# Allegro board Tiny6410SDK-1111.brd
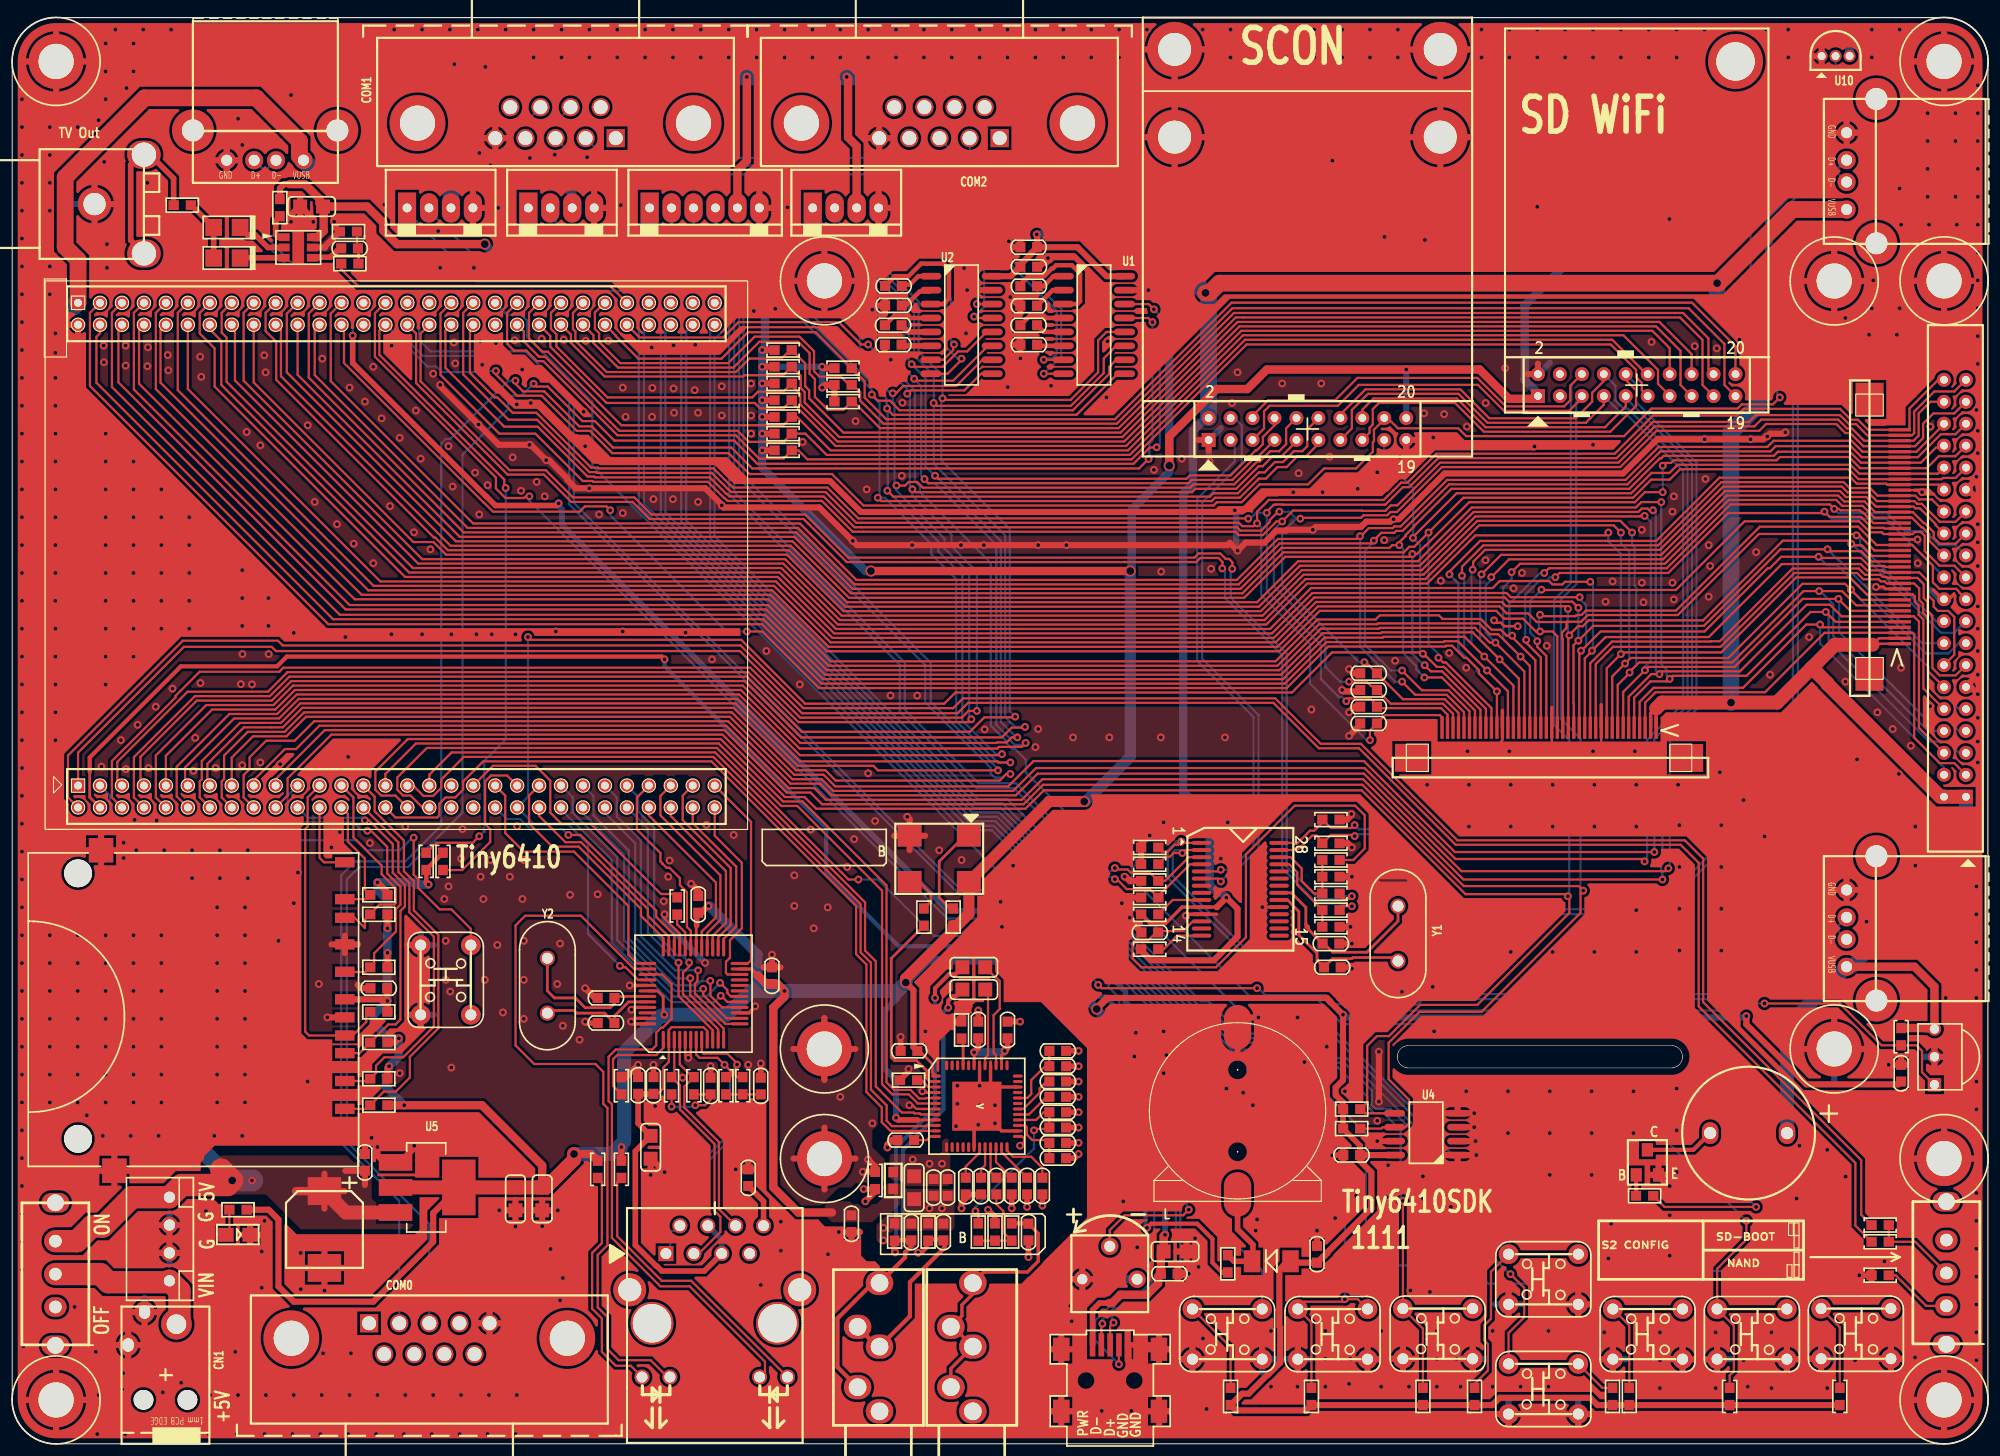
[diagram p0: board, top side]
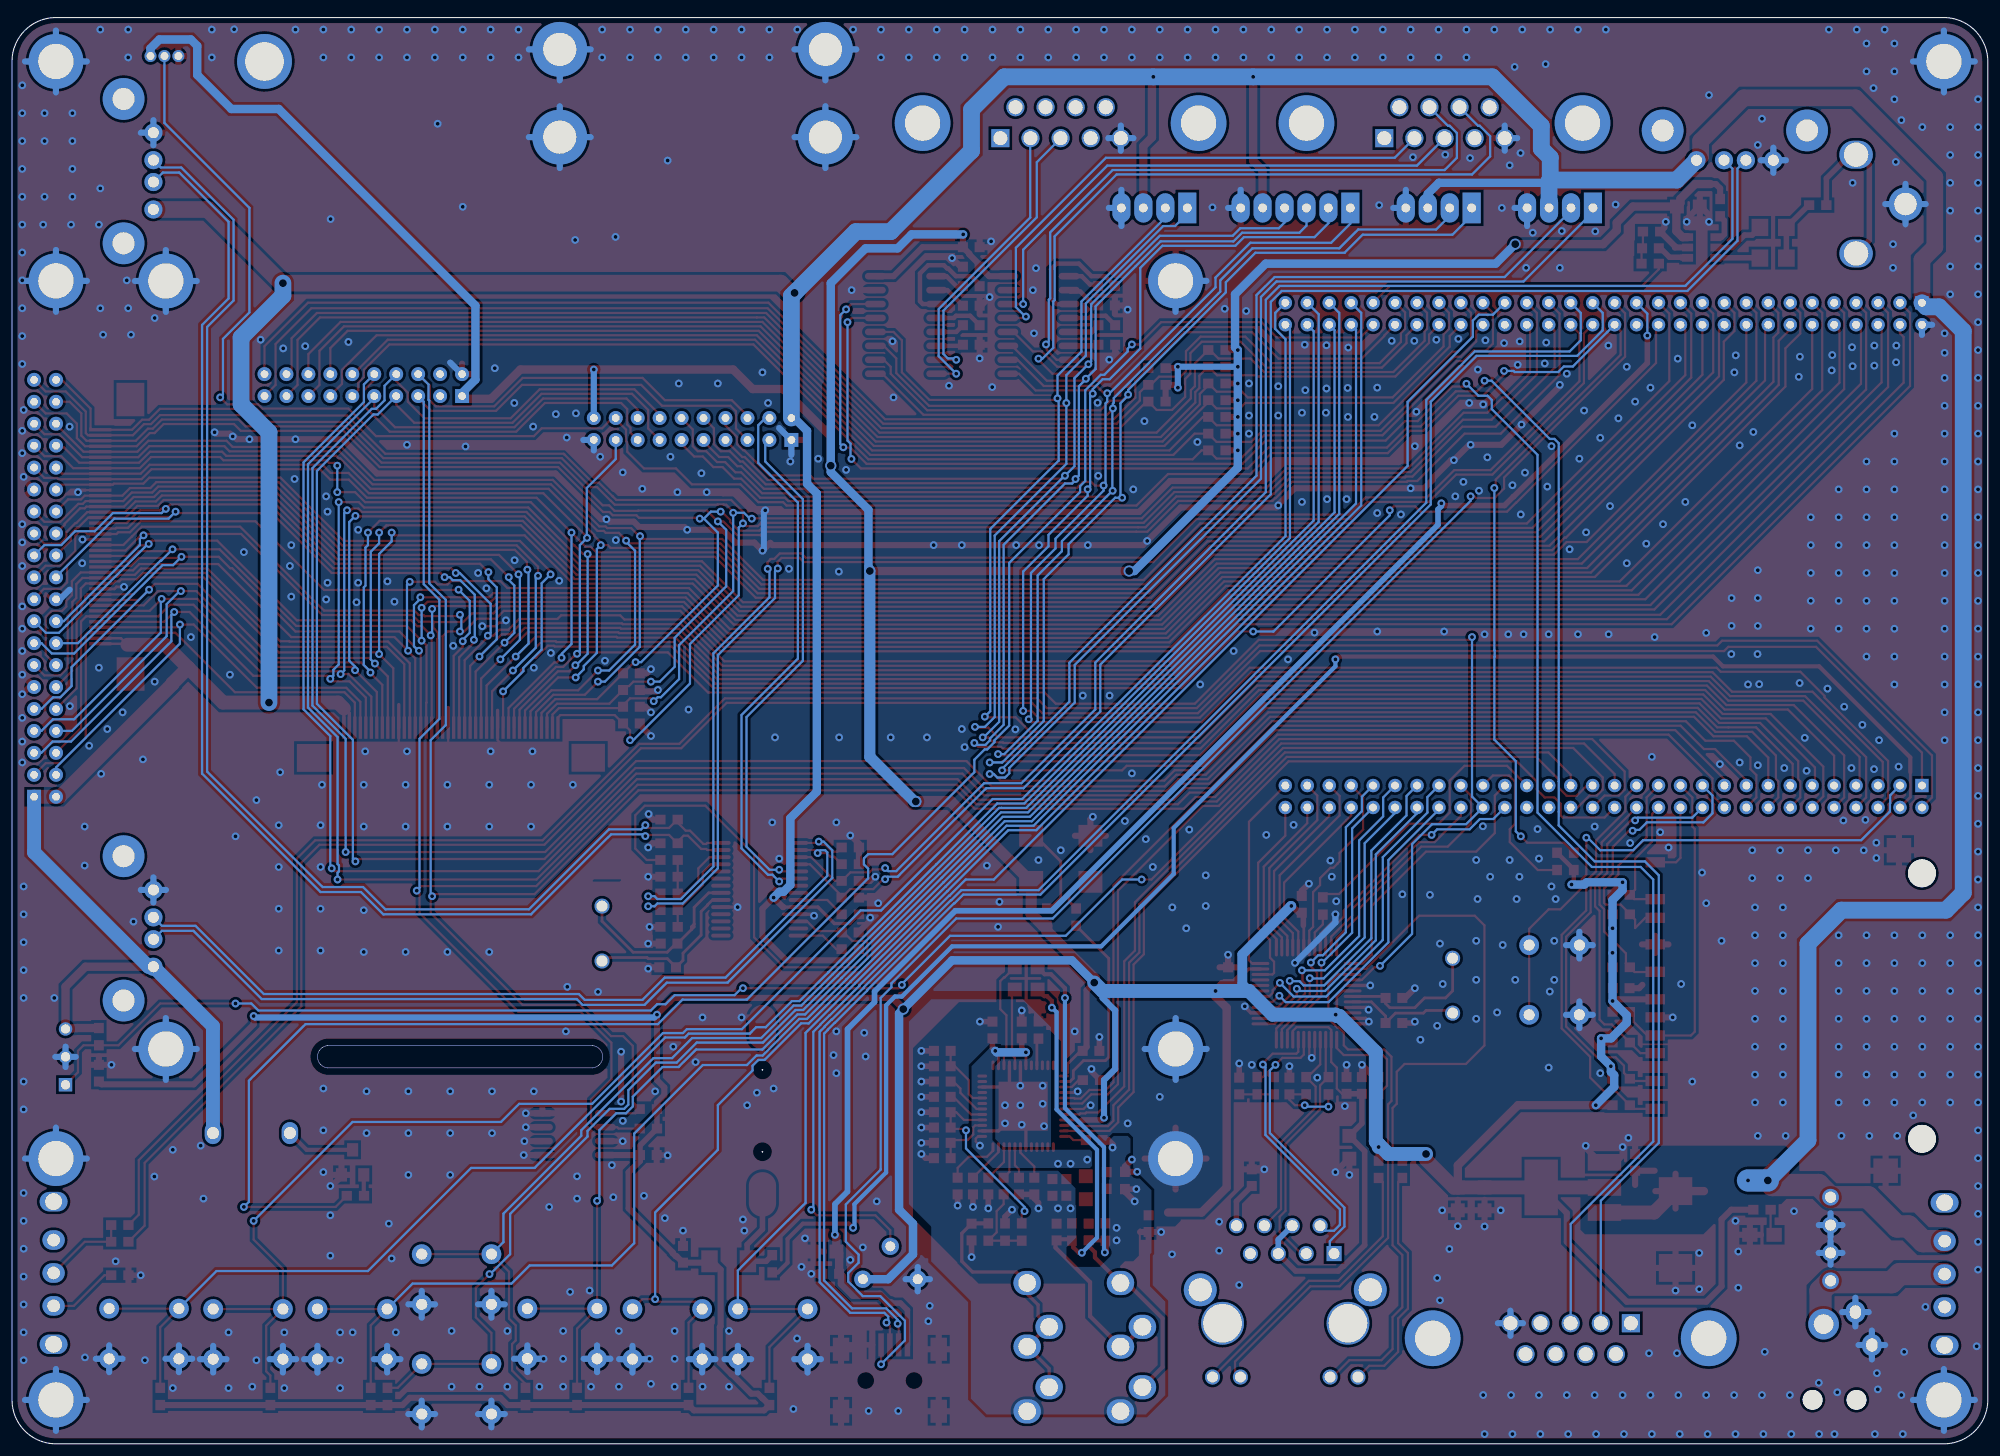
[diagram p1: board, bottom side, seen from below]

Outline 180 x 130 mm; copper layers: TOP, BOTTOM. Coordinates in mm from the lower left corner of the outline.
Outline path: 127.13,34.26 arc(126.19,35.28) 127.13,36.3 151.26,36.3 arc(152.17,35.28) 151.26,34.26 127.13,34.26

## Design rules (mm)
net group DIFFPAIR1: nets OTGDM OTGDP
net group DIFFPAIR2: nets USBDN USBDP
net group DIFFPAIR4: nets DM9000_TX+ DM9000_TX-
net group DIFFPAIR7: nets DM9000_RX+ DM9000_RX-
net group DIFFPAIR8: nets SUB_DM1 SUB_DP1
net group DIFFPAIR9: nets USB_D+ USB_D-
net group DIFFPAIR10: nets SUB_DM2 SUB_DP2
net group DIFFPAIR11: nets SUB_DM3 SUB_DP3
net group PWR: nets GND GND_AC97 VDD5V VDD33V

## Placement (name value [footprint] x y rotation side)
BAT1  BATTERY  [BAT600]  111.63 22.73 180 top
BUZZER  -  [SPEAKER]  161.44 28.32 180 top
C1  47uF/10V  [CAPSOP]  28.45 23.03 270 top
C2  47uF/10V  [C0805]  48.29 23.37 270 top
C3  104  [C0603]  32.13 24.89 90 top
C4  104  [0603A]  81.05 105.54 180 top
C5  104  [0603A]  81.05 103.76 180 top
C6  104  [0603A]  81.03 100.18 180 top
C7  104  [0603A]  79.5 101.96 0 top
C8  104  [0603A]  62.5 48.41 90 top
C14  104  [C0603]  93.37 107.29 180 top
C15  104  [C0603]  32.64 41.53 0 top
C16  104  [C0603]  76.45 19.3 90 top
C17  10uF/16V  [C0805]  104.9 17.53 0 top
C18  104  [C0603]  106.17 15.49 180 top
C20  104  [C0603]  118.87 18.03 270 top
C21  104  [C0603]  121.27 26.32 0 top
C22  104  [C0603]  83.95 22.61 90 top
C23  104  [C0603]  96.01 35.81 180 top
C24  104  [C0603]  85.22 22.61 90 top
C25  104  [C0603]  96.01 26.04 180 top
C26  104  [C0603]  96.01 28.83 180 top
C27  220pF  [C0603]  92.58 18.54 90 top
C28  220pF  [C0603]  84.84 18.54 90 top
C29  220pF  [C0603]  81.92 18.54 90 top
C30  104  [C0603]  104.39 46.61 180 top
C31  15pF  [C0603]  119.38 45.59 0 top
C32  10uF/10V  [C0805]  82.17 24.38 270 top
C33  1uF  [C0603]  93.85 24.26 270 top
C34  1uF  [C0603]  92.46 24.26 270 top
C35  104  [C0603]  57.02 33.43 270 top
C36  104  [C0603]  58.42 33.43 270 top
C37  1uF  [C0603]  89.66 24.26 270 top
C38  1uF  [C0603]  96.01 34.42 180 top
C39  1uF  [C0603]  96.01 27.43 180 top
C40  1uF  [C0603]  96.01 30.23 180 top
C41  47uF/10V  [C0805]  88.65 43.43 180 top
C42  47uF/10V  [C0805]  88.65 41.4 180 top
C43  100n  [C0603]  91.85 109.07 0 top
C44  104  [C0603]  31.5 108.97 180 top
C45  10uF/16V  [C0805]  28.32 112.78 180 top
C46  33uF  [C3216]  19.56 110.87 180 top
C47  33uF  [C3216]  19.56 108.08 180 top
C48  104  [C0603]  88.01 38.48 270 top
C49  104  [C0603]  90.68 38.48 270 top
C50  104  [C0603]  82.46 35.81 180 top
C51  104  [C0603]  88.27 22.73 90 top
C52  104  [C0603]  91.06 22.73 90 top
C53  104  [C0603]  86.87 22.73 90 top
C54  104  [0603A]  69.22 41.91 90 top
C55  104  [0603A]  93.37 105.51 180 top
C56  104  [0603A]  93.37 103.73 180 top
C57  104  [C0603]  96.01 31.62 180 top
C58  104  [0603A]  91.85 101.96 0 top
C59  104  [0603A]  93.37 100.18 180 top
C60  104  [C0603]  96.01 33.02 180 top
C61  104  [C0603]  80.64 27.69 0 top
C62  104  [C0603]  172.09 33.02 90 top
C64  15pF  [C0603]  119.51 43.43 0 top
C69  10nF  [0603A]  124.33 70.23 180 top
C70  10nF  [0603A]  124.33 67.18 180 top
C71  10nF  [0603A]  124.33 65.66 180 top
C72  10nF  [0603A]  124.33 68.71 180 top
C73  10uF/16V  [C0805]  45.85 23.37 270 top
C74  10uF/16V  [C0805]  58.17 28.07 270 top
C75  15pF  [C0603]  53.34 40.64 0 top
C76  15pF  [C0603]  53.34 38.35 0 top
C145  0.1uF  [C0603]  67.06 23.5 90 top
C148  104  [C0603]  68.2 33.38 270 top
C149  104  [C0603]  63.63 33.38 270 top
CN1  DC_JACK  [DC023B]  13.96 6.26 90 top
COM0  BOXCONN_DB9  [DB9RA_M]  38 10.99 90 top
COM1  BOXCONN_DB9  [DB9RA_M]  49.5 119.01 270 top
COM2  BOXCONN_DB9  [DB9RA_M]  84.47 119.01 270 top
CON1  CON4  [SIP4-FA2]  71.85 112.65 0 top
CON2  CON6  [SIP6-FA2]  63.07 112.65 0 top
CON3  CON4  [SIP4-FA2]  45.94 112.65 0 top
CON4  CON4  [SIP4-FA2]  34.89 112.65 0 top
CON5  HEADER 10X2  [SCON]  118 92.5 0 top
CON6  SD/MMC CARD  [NEWSD]  11.75 32.9 180 top
CON7  CON3  [TVOUT]  12 108.5 0 top
CON8  CON4  [CON4-B]  14.33 18.67 270 top
CON9  PHONEJACK STEREO SW  [EARJACK5]  78.92 15.83 270 top
CON10  PHONEJACK STEREO SW  [EARJACK5]  87.42 15.83 270 top
CON11  HEADER 10X2  [SDWIFI]  148 96.5 0 top
D1  1N4148  [D1206]  116.47 16.63 180 top
H1  CON1  [H1]  74 26 0 top
H2  CON1  [H1]  176 4 0 top
H3  CON1  [H1]  176 26 0 top
H4  CON1  [H1]  4 4 0 top
H5  CON1  [H1]  176 106 0 top
H6  CON1  [H1]  176 126 0 top
H7  CON1  [H1]  74 106 0 top
H8  CON1  [H1]  4 126 0 top
H9  CON1  [H1]  165.99 35.99 0 top
H10  CON1  [H1]  165.99 105.99 0 top
H11  CON1  [H1]  73.99 35.99 0 top
K1  -  [PUSHSW]  107.12 12.29 0 top
K2  -  [PUSHSW]  116.72 12.29 0 top
K3  -  [PUSHSW]  145.42 12.29 0 top
K4  -  [PUSHSW]  126.29 12.32 0 top
K5  -  [PUSHSW]  135.92 7.29 0 top
K6  -  [PUSHSW]  135.92 17.29 0 top
K7  -  [PUSHSW]  154.92 12.29 0 top
K8  -  [PUSHSW]  164.39 12.32 0 top
L1  F.B/120  [L0603]  80.26 24 90 top
LAN  -  [HR911105A]  64.01 21.49 180 top
LCD1  HEADER 20X2  [SMD40-0_5FA]  152.93 66.25 180 top
LCD2  HEADER 20X2  [SMD40-0_5FA]  172.93 69.76 90 top
LCD3  HEADER 20X2  [IDC40S]  177.99 58.97 90 top
LED_3V3  RED  [LED]  19.47 19.04 0 top
MINIUSB  USBOTG  [MINIUSB]  100.02 5.77 0 top
NOREF  -  []  -40.64 175.26 0 top
NOREF#2  -  []  0 0 0 top
Q1  9014  [SOT23FA]  148.97 25.65 0 top
R1  10K  [R0603]  37.72 53.09 90 top
R2  0R  [R0603]  170.18 18.41 0 top
R3  10K  [0603R]  33.4 39.37 0 top
R4  10K  [0603R]  33.4 50.04 0 top
R5  10K  [0603R]  122.03 28.73 180 top
R6  10K  [0603R]  33.4 48.26 0 top
R7  10K  [0603R]  33.4 43.43 0 top
R8  10K  [0603R]  122.03 30.51 180 top
R9  10K  [0603R]  33.4 36.58 0 top
R10  10K  [0603R]  33.4 33.27 0 top
R11  330  [0603R]  20.57 21.34 180 top
R12  10K  [0603R]  33.4 30.86 0 top
R13  100K  [0603R]  110.74 16.41 90 top
R14  0R  [R0603]  60.58 49.02 270 top
R15  6.8K,1%  [R0603]  55.5 32.64 270 top
R16  22R  [R0603]  120.14 48.64 180 top
R17  22R  [R0603]  120.14 50.16 180 top
R18  10K  [R0603]  70.23 90.55 180 top
R19  10K  [R0603]  70.23 93.6 180 top
R20  10K  [R0603]  70.23 96.65 180 top
R21  0R  [R0603]  170.18 19.94 0 top
R22  1K  [R0603]  170.18 15.37 180 top
R23  1.5K  [0603R]  148.72 22.61 180 top
R24  330R  [R0603]  53.34 25.02 90 top
R25  0R  [0603R]  91.06 19.3 270 top
R26  0R  [R0603]  78.61 24 270 top
R27  0R  [0603R]  83.06 48.01 90 top
R28  0R  [0603R]  81.66 33.15 180 top
R29  680  [0603R]  88.01 19.3 90 top
R30  47K  [0603R]  89.53 19.3 90 top
R31  47K  [0603R]  80.39 19.3 90 top
R32  47K  [0603R]  83.44 19.3 90 top
R33  10K  [0603R]  111 4.32 270 top
R34  100K  [0603R]  86.49 37.72 270 top
R35  10K  [0603R]  118.36 4.32 270 top
R36  10K  [0603R]  147.32 4.32 270 top
R37  10K  [0603R]  128.52 4.32 270 top
R38  10K  [0603R]  145.8 4.32 270 top
R39  330R  [R0603]  55.5 25.02 90 top
R40  10K  [0603R]  133.22 4.32 270 top
R41  4K7  [R0603]  39.24 53.09 90 top
R42  15K  [R0603]  103.63 48.26 0 top
R43  15K  [R0603]  103.63 45.09 0 top
R44  15K  [R0603]  120.14 54.74 0 top
R45  100K  [0603R]  85.72 48.01 270 top
R46  0R  [0603R]  15.49 112.9 180 top
R47  10K  [R0603]  156.46 4.32 270 top
R48  10K  [R0603]  166.5 4.32 270 top
R49  15K  [R0603]  120.14 56.9 0 top
R50  15K  [R0603]  103.63 54.36 180 top
R51  15K  [R0603]  103.63 52.83 180 top
R52  15K  [R0603]  103.63 51.31 180 top
R53  15K  [R0603]  103.63 49.78 180 top
R54  1K5  [R0603]  120.14 53.21 0 top
R59  50R  [0603R]  30.76 107.57 0 top
R60  150R  [0603R]  30.63 110.49 0 top
R61  4.7K  [0603R]  24.38 112.67 90 top
R62  51R  [R0603]  65.02 32.64 90 top
R66  51R  [R0603]  66.55 32.64 90 top
R67  51R  [R0603]  60.07 32.64 90 top
R68  51R  [R0603]  62.1 32.64 90 top
R71  10K  [R0603]  70.23 99.69 180 top
R72  10K  [R0603]  75.69 96.52 180 top
R73  10K  [R0603]  70.23 92.08 180 top
R74  10K  [R0603]  70.23 95.12 180 top
R75  10K  [R0603]  70.23 98.17 180 top
R76  10K  [R0603]  75.69 95 180 top
R77  10K  [R0603]  75.69 98.04 180 top
R78  10K  [R0603]  172.09 37.11 270 top
R79  15K  [R0603]  120.14 51.69 180 top
R80  15K  [R0603]  120.14 47.12 180 top
RST  -  [PUSHSW]  41.78 45.86 270 top
S1  CON5  [SW35]  3.94 15.49 270 top
S2  CON5  [SW35]  176.21 15.6 270 top
TINY6410  -  [TINY6410]  3 56 0 top
U1  MAX3232CSE  [SOP16]  95.76 106.43 0 top
U2  MAX3232CSE  [SOP16]  83.69 106.43 0 top
U4  AT24LC04  [SOP8]  131.68 26.32 180 top
U5  AMS1086CM-3.3  [SOT223S]  35.43 25.65 270 top
U6  UDA1341TS  [TSSOP28]  111.89 50.55 270 top
U7  WM9714LGEFL  [QFN48-19P7-TH]  87.88 30.77 270 top
U8  DM9000AEP  [LQFP48FA]  62.07 41.03 0 top
U9  NJM2561F1  [SOT-23-6]  26.06 109.04 270 top
U10  DS18B20  [TO-92B]  166.12 126.49 0 top
U12  IRM3638  [LEDIR-IRM3638]  175.12 35.27 90 top
USBH1  USB Port A type  [USB-A2]  167.12 112.5 270 top
USBH2  USB Port A type  [USB-A2]  167.12 43.48 270 top
USBH3  USB Port A type  [USB-A2]  26.54 116.99 0 top
W1  10K  [VR3_7X7]  98.85 16 0 top
Y1  12MHz  [OSC2PR-1]  126.25 44.07 90 top
Y2  25MHz  [OSC2PR-1]  48.76 44.2 270 top
Y5  24.576MHz  [Y7050]  87.35 55.57 180 top

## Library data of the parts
BAT1 = BAT600
BUZZER = SPEAKER
C1 = CAPSOP
C2 C73 C74 = C0805
C3 C14-C16 C18 C20-C31 C33-C40 C43 C44 C48-C53 C57 C60-C62 C64 C75 C76 C145 C148 C149 = C0603
C4-C8 C54-C56 C58 C59 C69-C72 = 0603A
C17 C32 C41 C42 C45 = C3216
C46 C47 = C1210
CN1 = DC023B
COM0-COM2 = DB9RA_M
CON1 CON3 CON4 = SIP4-FA2
CON2 = SIP6-FA2
CON5 = SCON
CON6 = NEWSD
CON7 = TVOUT
CON8 = CON4-B
CON9 CON10 = EARJACK5
CON11 = SDWIFI
D1 = D1206
H1-H11 = H1
K1-K8 RST = PUSHSW
L1 = L0603
LAN = HR911105A
LCD1 LCD2 = SMD40-0_5FA
LCD3 = IDC40S
LED_3V3 = LED
MINIUSB = MINIUSB
Q1 = SOT23FA
R1 R2 R14-R22 R24 R26 R39 R41-R44 R47-R54 R62 R66-R68 R71-R80 = R0603
R3-R13 R23 R25 R27-R38 R40 R45 R46 R59-R61 = 0603R
S1 S2 = SW35
TINY6410 = TINY6410
U1 U2 = SOP16
U4 = SOP8
U5 = SOT223S
U6 = TSSOP28
U7 = QFN48-19P7-TH
U8 = LQFP48FA
U9 = SOT-23-6
U10 = TO-92B
U12 = LEDIR-IRM3638
USBH1-USBH3 = USB-A2
W1 = VR3_7X7
Y1 Y2 = OSC2PR-1
Y5 = Y7050

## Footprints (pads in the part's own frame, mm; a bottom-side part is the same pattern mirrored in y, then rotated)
0603A
  rect 0.914x0.914 smd: 1(0,0) 2(1.524,0)
0603R
  rect 0.94x0.889 smd: 1(-0.787,0) 2(0.787,0)
BAT600
  oval 2.489x4.064 smd: 1(0,0) 2(0,-15.24)
  round 0.127 hole 1.194: 3(0,-3.886) 4(0,-11.354)
C0603
  rect 0.914x0.914 smd: 1(0,0) 2(1.524,0)
C0805
  rect 1.27x1.27 smd: 1(0,0) 2(2.083,0)
C3216
  rect 1.524x1.575 smd: 1(-1.206,0) 2(1.206,0)
CAPSOP
  rect 2.54x3.048 smd: 1(0,0) 2(7,0)
CON4-B
  round 1.524 hole 1.016: 1(-3.81,0) 2(-1.27,0) 3(1.27,0) 4(3.81,0)
D1206
  rect 1.5x2 smd: 1(0.009,-0.006) 2(3.51,-0.006)
DB9RA_M
  rect 1.651x1.651 hole 1.27: 1(0,5.486)
  round 1.651 hole 1.27: 2(0,2.743) 3(0,0) 4(0,-2.743) 5(0,-5.486) 6(-2.819,4.115) 7(-2.819,1.372) 8(-2.819,-1.372) 9(-2.819,-4.115)
  round 5.08 hole 3.2: 10(-1.372,12.573) 11(-1.372,-12.573)
DC023B
  round 1.803 hole 1.803 unplated: (-2.25,2) (-2.25,-2)
  round 2.794 hole 1.778: 1(4.65,-1)
  oval 1.981x1.778 hole 1.219x1.016: 2(5.75,1.9) 3(2.75,3.4)
EARJACK5
  oval 2.2x2.5 hole 1.6: 1(5.17,-1.903) 2(6.97,0.097) 3(1.17,0.097) 4(10.67,-1.903) 5(12.87,0.097)
H1
  round 5 hole 3.2: 1(0,0)
HR911105A
  round 3.9 hole 3.5 unplated: (-5.707,10.498) (5.723,10.498)
  rect 1.372x1.372 hole 0.991: 1(4.453,4.148)
  round 1.372 hole 0.991: 2(3.183,1.608) 3(1.913,4.148) 4(0.643,1.608) 5(-0.627,4.148) 6(-1.897,1.608) 7(-3.167,4.148) 8(-4.437,1.608) 9(6.633,15.398) 10(4.093,15.398) 11(-4.077,15.398) 12(-6.617,15.398)
  round 2.997 hole 2.1: 15(7.753,7.448) 16(-7.737,7.448)
IDC40S
  rect 1.27x1.27 hole 0.7: 1(0.011,-0.002)
  round 1.27 hole 0.7: 2(0.011,1.998) 3(2.011,-0.002) 4(2.011,1.998) 5(4.011,-0.002) 6(4.011,1.998) 7(6.011,-0.002) 8(6.011,1.998) 9(8.011,-0.002) 10(8.011,1.998) 11(10.011,-0.002) 12(10.011,1.998) 13(12.011,-0.002) 14(12.011,1.998) 15(14.011,-0.002) 16(14.011,1.998) 17(16.011,-0.002) 18(16.011,1.998) 19(18.011,-0.002) 20(18.011,1.998) 21(20.011,-0.002) 22(20.011,1.998) 23(22.011,-0.002) 24(22.011,1.998) 25(24.011,-0.002) 26(24.011,1.998) 27(26.011,-0.002) 28(26.011,1.998) 29(28.011,-0.002) 30(28.011,1.998) 31(30.011,-0.002) 32(30.011,1.998) 33(32.011,-0.002) 34(32.011,1.998) 35(34.011,-0.002) 36(34.011,1.998) 37(36.011,-0.002) 38(36.011,1.998) 39(38.011,-0.002) 40(38.011,1.998)
L0603
  rect 0.94x0.889 smd: 1(-0.762,0) 2(0.762,0)
LED
  rect 1.4x1.27 smd: 1(-0.002,0.008) 2(2.208,0.008)
LEDIR-IRM3638
  rect 1.219x1.219 hole 0.838: 1(-2.54,0)
  round 1.219 hole 0.838: 2(0,0) 3(2.54,0)
LQFP48FA
  oval 0.279x1.626 smd: 1(-2.75,-4.2) 2(-2.25,-4.2) 3(-1.75,-4.2) 4(-1.25,-4.2) 5(-0.75,-4.2) 6(-0.25,-4.2) 7(0.25,-4.2) 8(0.75,-4.2) 9(1.25,-4.2) 10(1.75,-4.2) 11(2.25,-4.2) 12(2.75,-4.2) 25(2.75,4.2) 26(2.25,4.2) 27(1.75,4.2) 28(1.25,4.2) 29(0.75,4.2) 30(0.25,4.2) 31(-0.25,4.2) 32(-0.75,4.2) 33(-1.25,4.2) 34(-1.75,4.2) 35(-2.25,4.2) 36(-2.75,4.2)
  oval 1.626x0.279 smd: 13(4.2,-2.75) 14(4.2,-2.25) 15(4.2,-1.75) 16(4.2,-1.25) 17(4.2,-0.75) 18(4.2,-0.25) 19(4.2,0.25) 20(4.2,0.75) 21(4.2,1.25) 22(4.2,1.75) 23(4.2,2.25) 24(4.2,2.75) 37(-4.2,2.75) 38(-4.2,2.25) 39(-4.2,1.75) 40(-4.2,1.25) 41(-4.2,0.75) 42(-4.2,0.25) 43(-4.2,-0.25) 44(-4.2,-0.75) 45(-4.2,-1.25) 46(-4.2,-1.75) 47(-4.2,-2.25) 48(-4.2,-2.75)
MINIUSB
  round 0 hole 0.889 unplated: (-2.2,0) (2.2,0)
  rect 0.508x2.108 smd: 1(-1.6,3.25) 2(-0.8,3.25) 3(0,3.25) 4(0.8,3.25) 5(1.6,3.25)
  rect 1.499x2.108 smd: 6(4.45,2.85) 7(-4.45,2.85) 8(-4.45,-2.8) 9(4.45,-2.8)
NEWSD
  round 2.54 hole 2.54 unplated: (5.748,5.104) (5.748,-19.095)
  rect 1.778x0.94 smd: 1(-18.552,-0.168) 2(-18.552,-2.708) 3(-18.552,-5.966) 4(-18.552,-7.612) 5(-18.552,-10.119) 6(-18.552,-12.619) 7(-18.552,-15.039) 8(-18.552,-16.744) 9(-18.552,2.372) 10(-18.552,-20.104) 11(-18.552,-4.315)
  rect 2.235x2.235 smd: 12(2.438,8.009) 13(3.653,-21.199)
OSC2PR-1
  round 1.372 hole 0.991: 1(-0.064,0) 2(4.94,0)
PUSHSW
  round 1.801 hole 1.001: 1(0.406,0) 2(6.756,0) 3(0.406,-4.572) 4(6.756,-4.572)
QFN48-19P7-TH
  oval 0.279x0.889 smd: 1(-2.75,-3.727) 2(-2.25,-3.727) 3(-1.75,-3.727) 4(-1.25,-3.727) 5(-0.75,-3.727) 6(-0.25,-3.727) 7(0.25,-3.727) 8(0.75,-3.727) 9(1.25,-3.727) 10(1.75,-3.727) 11(2.25,-3.727) 12(2.75,-3.727) 25(2.75,3.727) 26(2.25,3.727) 27(1.75,3.727) 28(1.25,3.727) 29(0.75,3.727) 30(0.25,3.727) 31(-0.25,3.727) 32(-0.75,3.727) 33(-1.25,3.727) 34(-1.75,3.727) 35(-2.25,3.727) 36(-2.75,3.727)
  oval 0.889x0.279 smd: 13(3.727,-2.75) 14(3.727,-2.25) 15(3.727,-1.75) 16(3.727,-1.25) 17(3.727,-0.75) 18(3.727,-0.25) 19(3.727,0.25) 20(3.727,0.75) 21(3.727,1.25) 22(3.727,1.75) 23(3.727,2.25) 24(3.727,2.75) 37(-3.727,2.75) 38(-3.727,2.25) 39(-3.727,1.75) 40(-3.727,1.25) 41(-3.727,0.75) 42(-3.727,0.25) 43(-3.727,-0.25) 44(-3.727,-0.75) 45(-3.727,-1.25) 46(-3.727,-1.75) 47(-3.727,-2.25) 48(-3.727,-2.75)
  rect 4.47x4.47 smd: 49(0,0)
R0603
  rect 0.94x0.889 smd: 1(-0.787,0) 2(0.787,0)
SCON
  rect 1.27x1.27 hole 0.7: 1(-9,-1)
  round 1.27 hole 0.7: 2(-9,1) 3(-7,-1) 4(-7,1) 5(-5,-1) 6(-5,1) 7(-3,-1) 8(-3,1) 9(-1,-1) 10(-1,1) 11(1,-1) 12(1,1) 13(3,-1) 14(3,1) 15(5,-1) 16(5,1) 17(7,-1) 18(7,1) 19(9,-1) 20(9,1)
  round 5 hole 3: A(12.1,34.6) B(12.1,26.6) C(-12.1,26.6) D(-12.1,34.6)
SDWIFI
  rect 1.27x1.27 hole 0.7: 1(-9,-1)
  round 1.27 hole 0.7: 2(-9,1) 3(-7,-1) 4(-7,1) 5(-5,-1) 6(-5,1) 7(-3,-1) 8(-3,1) 9(-1,-1) 10(-1,1) 11(1,-1) 12(1,1) 13(3,-1) 14(3,1) 15(5,-1) 16(5,1) 17(7,-1) 18(7,1) 19(9,-1) 20(9,1)
  round 5 hole 3.5: A(9,29.5)
SIP4-FA2
  rect 1.651x2.8 hole 0.8: 1(1.08,0)
  oval 1.651x2.667 hole 0.8: 2(3.08,0) 3(5.08,0) 4(7.08,0)
SIP6-FA2
  rect 1.651x2.8 hole 0.8: 1(-5,0)
  oval 1.651x2.667 hole 0.8: 2(-3,0) 3(-1,0) 4(1,0) 5(3,0) 6(5,0)
SMD40-0_5FA
  rect 0.305x2.032 smd: 1(3.16,0.968) 2(3.66,0.968) 3(4.16,0.968) 4(4.66,0.968) 5(5.16,0.968) 6(5.66,0.968) 7(6.161,0.968) 8(6.661,0.968) 9(7.161,0.968) 10(7.661,0.968) 11(8.161,0.968) 12(8.661,0.968) 13(9.161,0.968) 14(9.661,0.968) 15(10.162,0.968) 16(10.662,0.968) 17(11.162,0.968) 18(11.662,0.968) 19(12.162,0.968) 20(12.662,0.968) 21(13.162,0.968) 22(13.662,0.968) 23(14.163,0.968) 24(14.663,0.968) 25(15.163,0.968) 26(15.663,0.968) 27(16.163,0.968) 28(16.663,0.968) 29(17.163,0.968) 30(17.663,0.968) 31(18.164,0.968) 32(18.664,0.968) 33(19.164,0.968) 34(19.664,0.968) 35(20.164,0.968) 36(20.664,0.968) 37(21.164,0.968) 38(21.664,0.968) 39(22.165,0.968) 40(22.665,0.968)
  rect 3.048x2.54 smd: A(0.399,3.726) B(25.42,3.713)
SOP8
  oval 1.905x0.61 smd: 1(0,0) 2(0,-1.27) 3(0,-2.54) 4(0,-3.81) 5(5.74,-3.81) 6(5.74,-2.54) 7(5.74,-1.27) 8(5.74,0)
SOP16
  oval 1.905x0.61 smd: 1(0,0) 2(0,-1.27) 3(0,-2.54) 4(0,-3.81) 5(0,-5.08) 6(0,-6.35) 7(0,-7.62) 8(0,-8.89) 9(5.588,-8.89) 10(5.588,-7.62) 11(5.588,-6.35) 12(5.588,-5.08) 13(5.588,-3.81) 14(5.588,-2.54) 15(5.588,-1.27) 16(5.588,0)
SOT23FA
  rect 1.016x1.219 smd: B(-1.016,-1.143) C(0,1.143) E(1.016,-1.143)
SOT223S
  rect 1.524x3.048 smd: 1(0,-0.508) 2(2.286,-0.508) 3(4.572,-0.508)
  rect 5.08x3.048 smd: 4(2.286,5.258)
SOT-23-6
  rect 0.711x1.016 smd: 1(-0.94,-1.295) 2(0,-1.295) 3(0.94,-1.295) 4(0.94,1.295) 5(0,1.295) 6(-0.94,1.295)
SPEAKER
  oval 1.5x2 hole 1.1: 1(-0.254,0) 2(6.754,0)
SW35
  oval 1.778x2.54 hole 1.524: 1(-6.477,0) 5(6.523,0)
  oval 1.778x2.032 hole 1.143: 2(-2.977,0) 3(0.023,0) 4(3.023,0)
TINY6410
  rect 1.219x1.219 hole 0.711: A1(3,48) B1(3,4)
  round 1.219 hole 0.711: A2(3,46) A3(5,48) A4(5,46) A5(7,48) A6(7,46) A7(9,48) A8(9,46) A9(11,48) A10(11,46) A11(13,48) A12(13,46) A13(15,48) A14(15,46) A15(17,48) A16(17,46) A17(19,48) A18(19,46) A19(21,48) A20(21,46) A21(23,48) A22(23,46) A23(25,48) A24(25,46) A25(27,48) A26(27,46) A27(29,48) A28(29,46) A29(31,48) A30(31,46) A31(33,48) A32(33,46) A33(35,48) A34(35,46) A35(37,48) A36(37,46) A37(39,48) A38(39,46) A39(41,48) A40(41,46) A41(43,48) A42(43,46) A43(45,48) A44(45,46) A45(47,48) A46(47,46) A47(49,48) A48(49,46) A49(51,48) A50(51,46) A51(53,48) A52(53,46) A53(55,48) A54(55,46) A55(57,48) A56(57,46) A57(59,48) A58(59,46) A59(61,48) A60(61,46) B2(3,2) B3(5,4) B4(5,2) B5(7,4) B6(7,2) B7(9,4) B8(9,2) B9(11,4) B10(11,2) B11(13,4) B12(13,2) B13(15,4) B14(15,2) B15(17,4) B16(17,2) B17(19,4) B18(19,2) B19(21,4) B20(21,2) B21(23,4) B22(23,2) B23(25,4) B24(25,2) B25(27,4) B26(27,2) B27(29,4) B28(29,2) B29(31,4) B30(31,2) B31(33,4) B32(33,2) B33(35,4) B34(35,2) B35(37,4) B36(37,2) B37(39,4) B38(39,2) B39(41,4) B40(41,2) B41(43,4) B42(43,2) B43(45,4) B44(45,2) B45(47,4) B46(47,2) B47(49,4) B48(49,2) B49(51,4) B50(51,2) B51(53,4) B52(53,2) B53(55,4) B54(55,2) B55(57,4) B56(57,2) B57(59,4) B58(59,2) B59(61,4) B60(61,2)
TO-92B
  round 1.092 hole 0.711: 1(-1.27,0) 2(0,0) 3(1.27,0)
TSSOP28
  oval 0.356x1.778 smd: 1(-4.227,-3.531) 2(-3.576,-3.531) 3(-2.926,-3.531) 4(-2.276,-3.531) 5(-1.626,-3.531) 6(-0.975,-3.531) 7(-0.325,-3.531) 8(0.325,-3.531) 9(0.975,-3.531) 10(1.626,-3.531) 11(2.276,-3.531) 12(2.926,-3.531) 13(3.576,-3.531) 14(4.227,-3.531) 15(4.227,3.531) 16(3.576,3.531) 17(2.926,3.531) 18(2.276,3.531) 19(1.626,3.531) 20(0.975,3.531) 21(0.325,3.531) 22(-0.325,3.531) 23(-0.975,3.531) 24(-1.626,3.531) 25(-2.276,3.531) 26(-2.926,3.531) 27(-3.576,3.531) 28(-4.227,3.531)
TVOUT
  oval 3.048x2.54 hole 2.21: 1(0,0) 2(0,9)
  round 3.048 hole 2.032: 3(-4.5,4.5)
USB-A2
  round 1.651 hole 1: 1(0,0) 2(-2.504,0) 3(-4.498,0) 4(-7,0)
  round 3.81 hole 2: 5(3.084,2.718) 6(-10.074,2.718)
VR3_7X7
  round 1.575 hole 0.9: 1(-1.36,-1) 2(3.64,-1) 3(1.14,2)
Y7050
  rect 2.184x1.981 smd: 1(0.2,0.15) 2(5.6,0.15) 3(5.6,4.35) 4(0.2,4.35)

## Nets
GND: BAT1.2 C1.2 C2.2 C3.2 C5.2 C6.2 C8.2 C14.1 C15.1 C16.1 C17.2 C18.1 C20.1 C21.1 C30.2 C31.2 C35.1 C36.1 C43.1 C45.2 C50.2 C54.2 C56.2 C59.2 C62.2 C64.2 C69.2 C70.2 C71.2 C72.2 C73.2 C74.2 C75.1 C76.1 C145.2 C148.1 C149.1 CN1.2 CN1.3 COM0.5 COM1.5 COM2.5 CON1.4 CON2.6 CON3.4 CON4.4 CON5.1 CON5.19 CON5.A CON5.B CON5.C CON5.D CON6.3 CON6.6 CON6.12 CON6.13 CON7.3 CON8.2 CON8.3 CON11.2 H1.1 H2.1 H3.1 H4.1 H5.1 H6.1 H7.1 H8.1 H9.1 H10.1 H11.1 K1.3 K1.4 K2.3 K2.4 K3.3 K3.4 K4.3 K4.4 K5.3 K5.4 K6.3 K6.4 K7.3 K7.4 K8.3 K8.4 LCD1.11 LCD1.20 LCD1.29 LCD2.11 LCD2.20 LCD2.29 LCD3.11 LCD3.20 LCD3.29 LED_3V3.2 MINIUSB.5 MINIUSB.6 MINIUSB.7 MINIUSB.8 MINIUSB.9 Q1.E R15.1 R22.2 R26.1 R28.2 R34.1 R44.2 R49.2 R50.2 R51.2 R52.2 R53.2 R60.1 R79.1 R80.1 RST.3 RST.4 TINY6410.A2 U1.15 U2.15 U4.1 U4.2 U4.3 U4.4 U4.7 U5.1 U6.11 U6.19 U7.4 U7.7 U8.5 U8.6 U8.15 U8.33 U8.41 U8.45 U8.47 U8.48 U9.5 U10.1 U12.2 USBH1.4 USBH2.4 USBH3.4 W1.1 Y5.2
GND_AC97: C22.1 C23.1 C24.1 C25.1 C26.1 C27.1 C28.2 C29.2 C32.2 C33.2 C34.2 C38.1 C39.1 C40.1 C48.1 C49.1 C51.1 C52.1 C53.1 C57.1 C60.1 C61.1 CON9.5 CON10.5 R26.2 R30.2 R31.2 R32.2 U7.18 U7.26 U7.34 U7.40 U7.42 U7.49
GND_EARTH: C145.1 LAN.8
VBUS: C17.1 C18.2 MINIUSB.1 TINY6410.A27
VDD5V: BUZZER.1 C1.1 C3.1 CON1.3 CON2.5 CON3.3 CON4.3 CON5.2 CON8.1 LCD1.1 LCD1.2 LCD2.1 LCD2.2 LCD3.1 LCD3.2 R42.1 R43.1 R78.1 S1.2 TINY6410.A1 U5.3 U6.10 U12.3 USBH1.1 USBH2.1 USBH3.1
VDD33V: C2.1 C8.1 C14.2 C15.2 C16.2 C20.2 C21.2 C43.2 C45.1 C50.1 C54.1 C62.1 C73.1 CON5.20 CON6.4 CON11.1 D1.1 L1.1 R1.1 R3.2 R4.2 R5.2 R6.2 R7.2 R8.2 R9.2 R10.2 R11.1 R12.2 R18.2 R19.2 R20.2 R24.2 R33.2 R35.2 R36.2 R37.2 R38.2 R39.2 R40.2 R41.2 R45.2 R47.2 R48.2 R61.2 R71.2 R72.2 R73.2 R74.2 R75.2 R76.2 R77.2 U1.16 U2.16 U4.8 U5.2 U5.4 U7.1 U7.9 U8.23 U8.30 U8.42 U9.6 U10.3 W1.2 Y5.4
VDD_AC97: C22.2 C24.2 C32.1 C48.2 C49.2 L1.2 U7.13 U7.25 U7.38 U7.43
VDDBAT: BAT1.1 D1.2 R13.2
VDDIN: CN1.1 CON8.4 S1.3
VDDRTC: R13.1 TINY6410.B4
AC97_BITCLK: TINY6410.B29 U7.6
AC97_RSTN: TINY6410.B30 U7.11
AC97_SDI: TINY6410.B33 U7.8
AC97_SDO: TINY6410.B32 U7.5
AC97_SYNC: TINY6410.B31 U7.10
AIN0: TINY6410.A39 W1.3
AIN1: TINY6410.A40
CTSN1: CON2.2 CON5.9 TINY6410.B6 U2.9
DACOUT0: R59.1 TINY6410.A51
DM9000_RX+: LAN.3 R67.2 U8.3
DM9000_RX-: LAN.6 R68.2 U8.4
DM9000_TX+: LAN.1 R62.2 U8.7
DM9000_TX-: LAN.2 R66.2 U8.8
EINT0: K1.1 K1.2 R33.1 TINY6410.A53
EINT1: K2.1 K2.2 R35.1 TINY6410.A54
EINT2: K3.1 K3.2 R36.1 TINY6410.A55
EINT3: K4.1 K4.2 R37.1 TINY6410.A56
EINT4: K5.1 K5.2 R38.1 TINY6410.A57
EINT5: K6.1 K6.2 R40.1 TINY6410.A58
EINT7: TINY6410.B40 U8.34
EINT8: CON5.18 R1.2 TINY6410.A30 U10.2
EINT12: R78.2 TINY6410.B34 U12.1
EINT19: K7.1 K7.2 R47.1 TINY6410.A59
EINT20: K8.1 K8.2 R48.1 TINY6410.A60
GPE0: LCD1.30 LCD2.30 LCD3.30 TINY6410.A26
HPL: C29.1 C41.2 CON9.3 CON9.4 R31.1
HPR: C28.1 C42.2 CON9.1 CON9.2 R32.1
HSYNC: LCD1.35 LCD2.35 LCD3.35 TINY6410.A24
I2CSCL: CON5.5 CON11.5 R5.1 TINY6410.B19 U4.6
I2CSDA: CON5.6 CON11.6 R8.1 TINY6410.B20 U4.5
LADDR0: TINY6410.B35
LADDR1: TINY6410.B36
LADDR2: R14.1 TINY6410.B37
LADDR3: TINY6410.B38
LANLED: LAN.11 U8.39
LDATA0: TINY6410.B45 U8.18
LDATA1: TINY6410.B46 U8.17
LDATA2: TINY6410.B47 U8.16
LDATA3: TINY6410.B48 U8.14
LDATA4: TINY6410.B49 U8.13
LDATA5: TINY6410.B50 U8.12
LDATA6: TINY6410.B51 U8.11
LDATA7: TINY6410.B52 U8.10
LDATA8: TINY6410.B53 U8.31
LDATA9: TINY6410.B54 U8.29
LDATA10: TINY6410.B55 U8.28
LDATA11: TINY6410.B56 U8.27
LDATA12: TINY6410.B57 U8.26
LDATA13: TINY6410.B58 U8.25
LDATA14: TINY6410.B59 U8.24
LDATA15: TINY6410.B60 U8.22
LINKLED: LAN.10 U8.38
LNOE: TINY6410.B44 U8.35
LNWE: TINY6410.B43 U8.36
M_NRESET: RST.1 RST.2 TINY6410.B3
MIC: C37.2 R25.2 R29.1 R30.1
MICBIAS: C26.2 C40.2 R29.2 U7.28
NCS1: TINY6410.B39 U8.37
NET_AVDD25: C35.2 C36.2 C74.1 LAN.4 LAN.5 U8.2 U8.9
NETBUZZER/2: BUZZER.2 Q1.C
NETC4/1: C4.1 U2.1
NETC4/2: C4.2 U2.3
NETC5/1: C5.1 U2.2
NETC6/1: C6.1 U2.6
NETC33/1: C33.1 U7.24
NETC34/1: C34.1 U7.23
NETC37/1: C37.1 U7.21
NETC44/2: C44.2 U9.4
NETC51/2: C51.2 U7.20
NETC52/2: C52.2 U7.22
NETC53/2: C53.2 U7.19
NETC55/1: C55.1 U1.1
NETC55/2: C55.2 U1.3
NETC56/1: C56.1 U1.2
NETC57/2: C57.2 U7.29
NETC59/1: C59.1 U1.6
NETC60/2: C60.2 U7.30
NETC61/2: C61.2 U7.12
NETLAN/9: LAN.9 R24.1
NETLAN/12: LAN.12 R39.1
NETLED_3.3/1: LED_3V3.1 R11.2
NETR14/2: R14.2 U8.32
NETR23/2: Q1.B R23.2
NETR25/1: C27.2 CON10.1 CON10.2 CON10.3 CON10.4 R25.1
NETR27/1: R27.1 U7.2
NETR28/1: R28.1 U7.3
NETR42/2: R42.2 U6.9
NETR43/2: R43.2 U6.14
NETR45/1: R45.1 Y5.1
NETR46/1: C46.2 C47.2 R46.1
NETR46/2: CON7.1 CON7.2 R46.2
NETR54/2: C30.1 R54.2 U6.12
NETR59/2: C44.1 R59.2 R60.2
NETR62/1: C148.2 R62.1 R66.1
NETR67/1: C149.2 R67.1 R68.1
NETU1/4: C58.1 U1.4
NETU1/5: C58.2 U1.5
NETU2/4: C7.1 U2.4
NETU2/5: C7.2 U2.5
NETU7/27: C25.2 C39.2 U7.27
NETU7/32: C23.2 C38.2 U7.32
NETU7/39: C41.1 U7.39
NETU7/41: C42.1 U7.41
NETU7/45: R34.2 U7.45
NETU8/1: R15.2 U8.1
NETU8/43: C75.2 U8.43 Y2.1
NETU8/44: C76.2 U8.44 Y2.2
NETU9/1: R61.1 U9.1
NETU9/2: C46.1 U9.2
NETU9/3: C47.1 U9.3
NETY5/3: R27.2 Y5.3
NRESET: CON5.17 LCD1.32 LCD2.32 LCD3.32 TINY6410.B42 U8.40
NWAIT: R41.1 TINY6410.B41
OM3: R2.1 TINY6410.B1
OM4: R21.1 TINY6410.B2
OM34: R2.2 R21.2 S2.3
OTGDM: MINIUSB.2 TINY6410.A31
OTGDP: MINIUSB.3 TINY6410.A33
OTGDRV_VBUS: TINY6410.A28
OTGID: MINIUSB.4 TINY6410.A29
PWM0: R23.1 TINY6410.A52
PWM1: LCD1.31 LCD2.31 LCD3.31 TINY6410.A22
RSCTS1: COM1.8 U2.8
RSRTS1: COM1.7 U2.7
RSRXD0: COM0.2 U1.13
RSRXD1: COM1.2 U2.13
RSRXD2: COM2.2 U1.8
RSTXD0: COM0.3 U1.14
RSTXD1: COM1.3 U2.14
RSTXD2: COM2.3 U1.7
RTSN1: CON2.1 CON5.10 TINY6410.B5 U2.10
RXD0: CON1.2 TINY6410.B8 U1.12
RXD1: CON2.4 CON5.8 TINY6410.B10 U2.12
RXD2: CON3.2 CON5.12 TINY6410.B12 U1.9
RXD3: CON4.2 TINY6410.B14
SD0_CLK: CON6.5 R7.1 TINY6410.B21
SD0_CMD: CON6.2 R9.1 TINY6410.B22
SD0_DAT0: CON6.7 R6.1 TINY6410.B25
SD0_DAT1: CON6.8 R4.1 TINY6410.B26
SD0_DAT2: CON6.9 R12.1 TINY6410.B27
SD0_DAT3: CON6.1 R10.1 TINY6410.B28
SD0_NCD: CON6.11 R3.1 TINY6410.B23
SD0_NWP: CON6.10 TINY6410.B24
SD1_CLK: CON11.13 R19.1 TINY6410.A43
SD1_CMD: CON11.14 R74.1 TINY6410.A44
SD1_DAT0: CON11.17 R71.1 TINY6410.A47
SD1_DAT1: CON11.18 R76.1 TINY6410.A48
SD1_DAT2: CON11.19 R72.1 TINY6410.A49
SD1_DAT3: CON11.20 R77.1 TINY6410.A50
SD1_NCD: CON11.15 R20.1 TINY6410.A45
SD1_NWP: CON11.16 R75.1 TINY6410.A46
SDBOOT: R22.1 S2.4
SPICLK: CON5.16 CON11.9 TINY6410.B17
SPICS: CON5.15 CON11.10 TINY6410.B18
SPIMISO: CON5.14 CON11.8 TINY6410.B16
SPIMOSI: CON5.13 CON11.7 TINY6410.B15
SUB_DM1: R44.1 U6.27 USBH1.2
SUB_DM2: R50.1 U6.1 USBH2.2
SUB_DM3: R52.1 U6.3 USBH3.2
SUB_DP1: R49.1 U6.28 USBH1.3
SUB_DP2: R51.1 U6.2 USBH2.3
SUB_DP3: R53.1 U6.4 USBH3.3
TSXM: C69.1 LCD1.37 LCD2.37 LCD3.37 TINY6410.A36
TSXP: C72.1 LCD1.38 LCD2.38 LCD3.38 TINY6410.A35
TSYM: C70.1 LCD1.39 LCD2.39 LCD3.39 TINY6410.A38
TSYP: C71.1 LCD1.40 LCD2.40 LCD3.40 TINY6410.A37
TXD0: CON1.1 TINY6410.B7 U1.11
TXD1: CON2.3 CON5.7 TINY6410.B9 U2.11
TXD2: CON3.1 CON5.11 TINY6410.B11 U1.10
TXD3: CON4.1 TINY6410.B13
USB_D+: CON5.4 U6.6
USB_D-: CON5.3 U6.5
USBDN: R16.1 TINY6410.A32
USBDP: R17.1 TINY6410.A34
USBH_D+: R17.2 R54.1 R79.2 U6.26
USBH_D-: R16.2 R80.2 U6.25
VCLK: LCD1.36 LCD2.36 LCD3.36 TINY6410.A25
VD0: LCD1.3 LCD2.3 LCD3.3
VD1: LCD1.4 LCD2.4 LCD3.4
VD2: LCD1.5 LCD2.5 LCD3.5 TINY6410.A20
VD3: LCD1.6 LCD2.6 LCD3.6 TINY6410.A19
VD4: LCD1.7 LCD2.7 LCD3.7 TINY6410.A18
VD5: LCD1.8 LCD2.8 LCD3.8 TINY6410.A17
VD6: LCD1.9 LCD2.9 LCD3.9 TINY6410.A16
VD7: LCD1.10 LCD2.10 LCD3.10 TINY6410.A15
VD8: LCD1.12 LCD2.12 LCD3.12
VD9: LCD1.13 LCD2.13 LCD3.13
VD10: LCD1.14 LCD2.14 LCD3.14 TINY6410.A14
VD11: LCD1.15 LCD2.15 LCD3.15 TINY6410.A13
VD12: LCD1.16 LCD2.16 LCD3.16 TINY6410.A12
VD13: LCD1.17 LCD2.17 LCD3.17 TINY6410.A11
VD14: LCD1.18 LCD2.18 LCD3.18 TINY6410.A10
VD15: LCD1.19 LCD2.19 LCD3.19 TINY6410.A9
VD16: LCD1.21 LCD2.21 LCD3.21
VD17: LCD1.22 LCD2.22 LCD3.22
VD18: LCD1.23 LCD2.23 LCD3.23 TINY6410.A8
VD19: LCD1.24 LCD2.24 LCD3.24 TINY6410.A7
VD20: LCD1.25 LCD2.25 LCD3.25 TINY6410.A6
VD21: LCD1.26 LCD2.26 LCD3.26 TINY6410.A5
VD22: LCD1.27 LCD2.27 LCD3.27 TINY6410.A4
VD23: LCD1.28 LCD2.28 LCD3.28 TINY6410.A3
VDEN: LCD1.33 LCD2.33 LCD3.33 TINY6410.A21
VSYNC: LCD1.34 LCD2.34 LCD3.34 TINY6410.A23
WIFI_IO: CON11.11 R18.1 TINY6410.A41
WIFI_PD: CON11.12 R73.1 TINY6410.A42
X1: C31.1 U6.21 Y1.2
X2: C64.1 U6.20 Y1.1

Pads without a net: BAT1 3 4; COM0 1 4 6 7 8 9 10 11; COM1 1 4 6 9 10 11; COM2 1 4 6 7 8 9 10 11; CON11 3 4 A; LAN 7 15 16; LCD1 A B; LCD2 A B; S1 1 4 5; S2 1 2 5; U6 7 8 13 15 16 17 18 22 23 24; U7 14 15 16 17 31 33 35 36 37 44 46 47 48; U8 19 20 21 46; USBH1 5 6; USBH2 5 6; USBH3 5 6

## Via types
v1: diameter 0.711, hole 0.356, TOP to BOTTOM, 1145 vias
v2: diameter 1.016, hole 0.711, TOP to BOTTOM, 12 vias

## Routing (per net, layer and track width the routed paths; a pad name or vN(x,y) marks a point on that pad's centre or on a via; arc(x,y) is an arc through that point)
GND: length 1132.3
  TOP w0.203: U7.7 82.38,30.52 82.04,30.86 v1(81.73,30.86) ; U8.6 61.82,35.4 v1(61.59,35.18) 61.32,35.46 U8.5 ; 135.15,63.53 135.76,64.14 LCD1.29 ; v1(173.99,86.74) 173.81,86.93 LCD2.29 ; v1(128.7,109.73) 128.7,109.7 ; 140.26,63.3 LCD1.20 ; v1(59.44,48.26) 59.44,47.88 60.82,46.5 U8.33 ; 111.51,81.41 110.74,82.17 ; 144.77,62.74 LCD1.11
  TOP w0.229: LCD2.20 173.58,82.42 v1(173.58,82.43) 173.55,82.45 ; v1(135,75.06) 135.22,74.84 135.62,74.84 135.94,74.52 v1(137.16,74.52)
  TOP w0.254: LCD2.11 170.67,77.92 170.49,78.11 v1(169.8,78.11) ; v1(82.91,32.13) 83.19,32.13 83.3,32.02 U7.4
  TOP w0.305: U8.47 56.69,38.78 v1(56.39,38.48) 56.59,38.28 U8.48 ; 175.01,77.85 175.88,76.98 LCD3.20 176.42,76.98 176.91,77.47 ; v1(67.69,39.88) 67.44,39.62 67.44,39.57 67.14,39.28 U8.15 ; 135.76,66.85 LCD1.29 ; U8.45 56.63,39.78 v1(56.41,39.57) ; LCD1.11 144.77,67.38 ; v1(106.93,48.13) 107.07,48.27 U6.11 109.72,48.27 ; U8.41 v1(56.26,41.78) ; LCD1.20 140.26,67.11 ; U6.19 v1(113.89,48.92)
  TOP w0.508: 101.73,6.88 101.73,8.91 MINIUSB.5 104.07,9.02 MINIUSB.6 ; U4.7 v1(124.36,27.59) ; C149.1 v1(63.63,34.42) ; v1(81.66,34.16) 81.66,33.93 R28.2 ; v1(52.2,38.48) 52.32,38.35 C76.1 ; C36.1 v1(58.42,34.54) ; v1(107.76,18.73) 107.76,16.45 v1(108.08,16.13) ; C21.1 120.3,26.32 v1(120.27,26.29) ; R22.2 v1(168.28,15.37) ; C148.1 v1(68.2,34.67) ; v1(80.94,37.08) C50.2 ; C35.1 v1(57.02,34.54)
  TOP w0.559: K3.4 153.39,7.71 ; K3.4 152.17,8.93 ; K3.4 150.96,7.71 ; K3.4 152.17,6.5 ; v1(151,23.5) 150.88,23.5 149.99,24.38 Q1.E ; W1.1 98.59,15 ; W1.1 96.38,15 ; W1.1 97.49,13.9 ; W1.1 97.49,16.11 ; 6.66,54.1 CON6.13 ; CON6.13 9.53,54.1 ; CON6.13 8.09,52.67 ; CON6.13 8.09,55.54 ; K4.3 127.92,7.75 ; K4.3 125.48,7.75 ; K4.3 126.7,8.97 ; K4.3 126.7,6.53 ; K1.3 107.52,8.93 ; K1.3 107.52,6.5 ; K1.3 108.74,7.71 ; K1.3 106.31,7.71 ; Q1.E 149.99,25.44 ; Q1.E 149.16,24.51 ; Q1.E 150.81,24.51 ; U4.4 v1(133.19,30.13) ; U4.4 130.41,30.13 ; U4.4 131.68,30.75 ; 171.15,6.53 K8.4 ; K8.4 171.15,8.97 ; K8.4 169.93,7.75 ; K8.4 172.37,7.75 ; COM1.5 44.01,120.15 ; COM1.5 45.15,119.01 ; COM1.5 42.87,119.01 ; COM1.5 44.01,117.86 ; v1(101.35,51.69) 101.45,51.69 101.83,51.31 R52.2 ; K3.3 145.82,8.93 ; K3.3 145.82,6.5 ; K3.3 144.61,7.71 ; CON4.4 43.12,112.65 ; CON4.4 41.97,114.3 ; CON4.4 41.97,111 ; 30.3,44.73 CON6.6 ; CON6.6 31.51,45.52 ; CON6.6 30.3,46.31 ; CON6.6 29.09,45.52 ; U4.3 v1(133.19,28.86) ; 85.62,38.38 86.61,38.38 86.61,39.24 ; 173.18,4 H2.1 ; H2.1 176,1.18 ; H2.1 176,6.82 ; H2.1 178.82,4 ; 155.32,6.5 K7.3 ; K7.3 155.32,8.93 ; K7.3 154.11,7.71 ; H4.1 6.82,4 ; H4.1 4,1.18 ; H4.1 1.18,4 ; H4.1 4,6.82 ; 37.21,37.89 RST.4 ; RST.4 37.21,40.32 ; RST.4 35.99,39.1 ; C16.1 77.23,19.3 ; C16.1 v1(75.31,19.3) ; C16.1 76.45,18.53 ; 141.46,12.71 K6.4 ; K6.4 142.67,11.5 ; K6.4 143.89,12.71 ; K6.4 142.67,13.93 ; 81.75,54.11 Y5.2 ; Y5.2 83.16,55.42 ; Y5.2 80.35,55.42 ; Y5.2 81.75,56.93 v1(81.53,57.15) ; 106.17,16.27 C18.1 106.17,14.72 ; CON8.2 15.41,19.94 ; CON8.2 13.25,19.94 ; CON8.2 14.33,18.86 ; C64.2 121.92,43.43 v1(122.05,43.31) ; 85.72,38.51 R34.1 86.49,39.29 ; 71.18,106 H7.1 ; H7.1 74,108.82 ; H7.1 74,103.18 ; H7.1 76.82,106 ; R79.1 v1(122.05,51.69) ; v1(90.93,104.52) 91.72,103.73 C56.2 ; 1.18,126 H8.1 ; H8.1 4,123.18 ; H8.1 4,128.82 ; H8.1 6.82,126 ; C73.2 45.85,22.24 ; C73.2 v1(44.37,21.29) ; C73.2 v1(45.85,19.81) ; C73.2 46.8,21.29 ; 91.85,102.96 C56.2 ; C56.2 91.85,104.51 ; U9.5 28.5,109.04 28.5,109.14 R60.1 29.46,110.87 29.46,111.25 v1(29.34,111.38) ; U4.1 v1(133.38,26.32) ; U4.1 131.68,25.7 ; U4.1 130.41,26.32 ; U10.1 164.85,127.36 ; U10.1 163.98,126.49 ; U10.1 164.85,125.63 ; 105.9,116.28 CON5.C ; CON5.C 108.72,119.1 ; CON5.C 105.9,121.92 ; CON5.C 103.08,119.1 ; v1(38.99,96.52) 38.99,96.39 v1(42.48,92.9) 44.32,91.06 v1(47.12,91.06) 47.24,91.06 v1(48.64,89.66) 48.9,89.66 50.57,87.99 50.57,87.87 51.34,87.1 v1(52.58,87.1) 63.14,87.1 64.64,85.6 v1(64.64,85.53) 64.83,85.34 73.53,85.34 v1(76.58,82.3) 76.96,81.92 v1(81.99,81.92) v1(86.44,81.92) v1(88.52,81.92) v1(93.47,81.92) v1(96.04,81.92) 110.72,81.92 110.92,82.12 v1(111.63,81.41) 112.37,82.14 114.08,82.14 115.18,83.24 116.04,83.24 116.12,83.31 v1(118.49,83.31) 118.75,83.57 122.87,83.57 123.35,84.05 125.53,84.05 125.68,84.2 125.78,84.2 v1(125.85,84.27) 125.86,84.28 126.33,84.28 130.49,88.44 146.75,88.44 149.87,91.57 v1(154.18,91.57) v1(158.37,91.57) 159.51,91.57 159.77,91.82 v1(159.89,91.82) 160.15,92.08 161.42,92.08 v1(161.54,92.2) ; 136.32,11.5 K6.3 136.32,13.93 ; C59.2 91.85,100.95 ; C59.2 v1(91.85,98.93) ; C59.2 91.07,100.18 ; U12.2 176.05,35.27 ; U12.2 175.12,36.2 ; U12.2 175.12,34.34 ; K7.4 161.67,8.93 ; K7.4 161.67,6.5 ; K7.4 162.89,7.71 ; K7.4 160.46,7.71 ; 73.99,33.17 H11.1 ; H11.1 71.17,35.99 ; H11.1 73.99,38.81 ; H11.1 76.81,35.99 ; K5.4 143.89,2.71 ; K5.4 141.46,2.71 ; K5.4 142.67,1.5 ; v1(57.02,34.54) 55.91,33.43 R15.1 ; 67.83,25.02 C145.2 67.06,25.79 ; H5.1 176,108.82 ; H5.1 176,103.18 ; H5.1 178.82,106 ; H5.1 173.18,106 ; C3.2 32.13,27.28 v1(32.74,27.89) ; CON5.B 130.1,121.92 ; CON5.B 127.28,119.1 ; CON5.B 132.92,119.1 ; CON5.B 130.1,116.28 ; v1(121.79,66.67) 122.3,67.18 C70.2 ; C72.2 122.68,68.58 121.28,68.58 v1(121.16,68.71) ; CN1.3 10.56,10.31 ; CN1.3 11.77,9.01 ; CN1.3 9.36,9.01 ; CN1.3 10.56,7.7 ; C15.1 31.78,41.53 31.47,41.83 ; 103.41,2.97 MINIUSB.9 ; MINIUSB.9 105.54,2.97 ; MINIUSB.9 104.48,4.34 ; MINIUSB.9 104.48,1.6 ; 130.1,124.28 CON5.A ; CON5.A 127.28,127.1 ; CON5.A 132.92,127.1 ; R44.2 121.67,54.74 v1(122.05,54.36) ; 135.11,2.71 K5.3 ; K5.3 137.54,2.71 ; K5.3 136.32,1.5 ; 112.66,7.71 K1.4 113.87,8.93 ; 21.68,18.1 LED_3V3.2 ; LED_3V3.2 20.66,19.05 ; LED_3V3.2 22.7,19.05 ; LED_3V3.2 21.68,20 ; 91.85,109.84 C43.1 91.07,109.07 ; 78.99,117.86 COM2.5 ; COM2.5 78.99,120.15 ; COM2.5 77.84,119.01 ; COM2.5 80.13,119.01 ; v1(178.94,88.14) 178.94,87.93 LCD3.29 178.17,86.98 179.1,86.06 ; 165.98,119.51 USBH1.4 ; USBH1.4 167.12,120.65 ; USBH1.4 167.12,118.36 ; USBH1.4 168.26,119.51 ; 121.27,25.54 C21.1 121.27,27.09 ; R49.2 121.62,56.9 122,57.28 v1(122,57.4) ; 127,90.55 CON5.19 127.95,91.5 ; 43.49,9.85 COM0.5 ; COM0.5 43.49,12.13 ; COM0.5 44.63,10.99 ; COM0.5 42.34,10.99 ; USBH3.4 20.68,116.99 ; USBH3.4 19.54,118.14 ; USBH3.4 19.54,115.85 ; USBH3.4 18.4,116.99 ; 79.53,102.98 C5.2 ; C5.2 78.74,103.76 v1(78.36,103.38) ; C5.2 79.53,104.53 ; 78.93,111 CON1.4 ; CON1.4 78.93,114.3 ; CON1.4 80.07,112.65 ; v1(52.2,41.53) 53.09,40.64 C75.1 ; v1(61.85,51.05) 62.5,50.4 C8.2 ; v1(101.09,49.28) 101.6,49.78 R53.2 ; 79.38,99.42 79.98,98.82 v1(80.04,98.82) 79.5,99.36 C6.2 ; C45.2 26.29,112.78 27.43,111.63 v1(27.43,111.38) ; C45.2 26.24,113.73 ; C45.2 26.24,111.82 ; C45.2 26.16,112.78 25.4,112.01 v1(25.4,111.38) ; CON7.3 7.5,114.84 ; CON7.3 7.5,111.16 ; CON7.3 9.34,113 ; v1(77.98,25.91) 78.61,25.27 R26.1 v1(77.5,24.79) ; C1.2 30.29,16.03 ; C1.2 v1(28.45,13.97) ; C1.2 26.61,16.03 ; C1.2 28.45,17.62 ; v1(179.07,68.33) 178.42,68.98 LCD3.11 177.99,69.03 v1(179.07,70.1) ; 68.44,43.43 C54.2 ; C54.2 69.99,43.43 ; C54.2 v1(69.22,44.58) ; USBH2.4 168.26,50.48 ; USBH2.4 167.12,49.34 ; USBH2.4 165.98,50.48 ; USBH2.4 167.12,51.63 ; v1(121.79,64.52) 122.81,65.53 C71.2 ; v1(36.63,27.16) 36.63,26.98 35.31,25.65 U5.1 33.91,25.65 33.27,26.29 v1(33.27,27.05) ; 53.02,111 CON3.4 ; CON3.4 54.16,112.65 ; CON3.4 53.02,114.3 ; 12.06,10.7 CN1.2 ; CN1.2 10.86,12.01 ; CN1.2 13.27,12.01 ; C2.2 48.29,22.24 ; C2.2 47.33,21.28 ; C2.2 v1(48.29,19.84) ; C2.2 v1(49.71,21.28) ; 104.48,7.25 MINIUSB.6 ; MINIUSB.6 104.48,9.99 ; MINIUSB.6 103.41,8.62 ; MINIUSB.6 105.54,8.62 ; 123.47,6.5 K2.4 ; K2.4 124.69,7.71 ; K2.4 122.26,7.71 ; K2.4 123.47,8.93 ; 138.05,97.5 CON11.2 139,98.45 ; v1(101.82,47.96) 101.89,47.88 101.89,47.62 102.87,46.64 C30.2 ; v1(94.36,108.08) 93.57,107.29 C14.1 ; 94.51,8.62 MINIUSB.7 ; MINIUSB.7 95.57,9.99 ; MINIUSB.7 95.57,7.25 ; MINIUSB.7 96.64,8.62 ; 164.8,6.53 K8.3 ; K8.3 164.8,8.97 ; K8.3 163.58,7.75 ; C20.1 v1(118.87,19.43) ; 6,101.07 TINY6410.A2 5.07,102 ; 37.21,44.24 RST.3 35.99,45.45 ; H9.1 168.81,35.99 ; H9.1 163.17,35.99 ; H9.1 165.99,38.81 ; 111.63,35.62 BAT1.2 ; BAT1.2 110.07,37.97 ; BAT1.2 111.76,37.97 112.65,38.86 v1(113.54,38.86) ; C62.2 v1(170.94,34.54) ; C62.2 172.09,35.32 ; C62.2 172.86,34.54 ; K4.4 133.05,8.97 ; K4.4 131.83,7.75 ; K4.4 133.05,6.53 ; v1(87,105.16) U2.15 ; 71.18,26 H1.1 ; H1.1 76.82,26 ; H1.1 74,23.18 ; H1.1 74,28.82 ; H3.1 176,28.82 ; H3.1 173.18,26 ; H3.1 178.82,26 ; 7.87,24.89 CON6.12 ; CON6.12 9.31,26.33 ; CON6.12 9.31,23.46 ; CON6.12 10.74,24.89 ; v1(124.51,31.19) v1(124.51,35.74) ; 95.57,1.6 MINIUSB.8 ; MINIUSB.8 96.64,2.97 ; MINIUSB.8 94.51,2.97 ; MINIUSB.8 95.57,4.34 ; 105.9,124.28 CON5.D ; CON5.D 103.08,127.1 ; CON5.D 108.72,127.1 ; U1.15 103.38,105.16 103.92,105.19 104.01,105.28 103.63,105.28 v1(103.5,105.16) ; 106.98,16.57 C17.2 ; C17.2 107.76,17.53 ; C17.2 106.03,17.53 ; C17.2 106.98,18.48 ; 169.39,14.61 R22.2 169.39,16.13 ; CON2.6 68.07,114.3 ; CON2.6 68.07,111 ; CON2.6 69.21,112.65 ; 173.18,126 H6.1 ; H6.1 176,128.82 ; H6.1 176,123.18 ; H6.1 178.82,126 ; 101.62,7.65 MINIUSB.5 101.62,10.39 ; H10.1 165.99,108.81 ; H10.1 163.17,105.99 ; H10.1 165.99,103.17 ; H10.1 168.81,105.99 ; 13.25,17.4 CON8.3 ; CON8.3 15.41,17.4 ; CON8.3 14.33,18.48 ; R51.2 R50.2 102.84,54.71 103.58,55.45 v1(103.63,55.45) ; 117.12,8.93 K2.3 117.12,6.5 ; R80.1 v1(121.92,47.12) ; v1(121.79,70.61) 122.17,70.23 C69.2 ; 108.05,91.5 CON5.1 109,90.55 ; CON6.3 v1(28.71,38.87) ; v1(138.68,90.91) 138.61,90.83 129.5,90.83 126.86,88.19 126.29,88.19 125.15,87.05 v1(122.58,87.05) 119.68,87.05 v1(119.38,86.74) v1(116.71,86.74) 115.32,86.74 115.22,86.64 113.74,86.64 112.19,85.09 v1(111.38,85.09) 111.23,84.94 77.32,84.94 74.5,87.76 65.91,87.76 65.66,88 65.62,88 64.13,89.48 53.68,89.48 53.6,89.56 53.57,89.56 v1(52.2,90.93) 51.38,91.75 50.81,91.75 47.76,94.79 47.43,94.79 47.35,94.87 v1(47.24,94.87) 47.14,94.87 47.06,94.79 46.02,94.79 v1(45.97,94.74) 45.85,94.87 45.59,94.87 43.66,96.8 43.54,96.8 43.05,97.3 43.05,97.41 42.98,97.49 42.98,98.2 v1(42.82,98.35) 42.65,98.53 v1(42.65,100.48) ; v1(58.17,24.51) C74.2 58.22,25.98 v1(59.44,24.77) ; U4.2 v1(133.32,27.59) ; C31.2 v1(122.05,45.59)
  TOP w0.762: C145.2 v1(65.91,25.02) ; C18.1 v1(107.19,15.49)
  BOTTOM w0.203: 124.33,88.54 v1(124.36,88.54)
  BOTTOM w0.559: H3.1 178.82,26 ; H3.1 176,28.82 ; H3.1 173.18,26 ; H4.1 6.82,4 ; H4.1 4,1.18 ; H4.1 1.18,4 ; H4.1 4,6.82 ; 97.49,13.9 W1.1 ; W1.1 96.38,15 ; W1.1 97.49,16.11 ; W1.1 98.59,15 ; K5.4 143.89,2.71 ; K5.4 141.46,2.71 ; K5.4 142.67,3.93 ; K5.4 142.67,1.5 ; H11.1 73.99,38.81 ; H11.1 71.17,35.99 ; H11.1 76.81,35.99 ; H11.1 73.99,33.17 ; 106.31,7.71 K1.3 ; K1.3 108.74,7.71 ; K1.3 107.52,6.5 ; K1.3 107.52,8.93 ; 68.07,114.3 CON2.6 69.21,112.65 ; 163.58,7.75 K8.3 ; K8.3 166.02,7.75 ; K8.3 164.8,6.53 ; K8.3 164.8,8.97 ; K3.3 145.82,8.93 ; K3.3 144.61,7.71 ; K3.3 145.82,6.5 ; K3.3 147.04,7.71 ; v1(111.63,81.41) 111.51,81.53 111.51,84.96 v1(111.38,85.09) ; 176,123.18 H6.1 ; H6.1 173.18,126 ; H6.1 178.82,126 ; H6.1 176,128.82 ; COM0.5 43.49,12.13 ; COM0.5 43.49,9.85 ; COM0.5 42.34,10.99 ; COM0.5 44.63,10.99 ; H9.1 168.81,35.99 ; H9.1 165.99,38.81 ; H9.1 163.17,35.99 ; H9.1 165.99,33.17 ; 78.93,111 CON1.4 ; CON1.4 78.93,114.3 ; CON1.4 80.07,112.65 ; v1(59.44,48.26) 59.44,47.52 v1(63.12,43.84) ; H8.1 4,128.82 ; H8.1 6.82,126 ; H8.1 1.18,126 ; H8.1 4,123.18 ; 10.86,12.01 CN1.2 ; CN1.2 12.06,13.31 ; CN1.2 12.06,10.7 ; CN1.2 13.27,12.01 ; 105.9,116.28 CON5.C ; CON5.C 105.9,121.92 ; CON5.C 103.08,119.1 ; CON5.C 108.72,119.1 ; 176,1.18 H2.1 ; H2.1 176,6.82 ; H2.1 173.18,4 ; H2.1 178.82,4 ; 175.12,34.34 U12.2 ; U12.2 175.12,36.2 ; U12.2 174.2,35.27 ; U12.2 176.05,35.27 ; 14.33,16.32 CON8.3 ; CON8.3 13.25,17.4 ; CON8.3 14.33,18.48 ; CON8.3 15.41,17.4 ; 125.48,7.75 K4.3 ; K4.3 127.92,7.75 ; K4.3 126.7,8.97 ; K4.3 126.7,6.53 ; COM2.5 78.99,120.15 ; COM2.5 78.99,117.86 ; COM2.5 77.84,119.01 ; COM2.5 80.13,119.01 ; 54.16,112.65 CON3.4 53.02,114.3 ; 103.08,127.1 CON5.D ; CON5.D 105.9,124.28 ; CON5.D 108.72,127.1 ; 71.18,106 H7.1 74,103.18 ; 18.4,116.99 USBH3.4 ; USBH3.4 19.54,115.85 ; USBH3.4 19.54,118.14 ; USBH3.4 20.68,116.99 ; 133.05,6.53 K4.4 ; K4.4 131.83,7.75 ; K4.4 133.05,8.97 ; K4.4 134.27,7.75 ; 37.21,44.24 RST.3 ; RST.3 38.43,45.45 ; RST.3 35.99,45.45 ; RST.3 37.21,46.67 ; 150.96,7.71 K3.4 ; K3.4 153.39,7.71 ; K3.4 152.17,8.93 ; K3.4 152.17,6.5 ; H5.1 178.82,106 ; H5.1 176,103.18 ; H5.1 173.18,106 ; H5.1 176,108.82 ; 169.93,7.75 K8.4 ; K8.4 171.15,6.53 ; K8.4 172.37,7.75 ; K8.4 171.15,8.97 ; 165.99,103.17 H10.1 ; H10.1 163.17,105.99 ; H10.1 168.81,105.99 ; H10.1 165.99,108.81 ; K2.3 117.12,8.93 ; K2.3 118.34,7.71 ; K2.3 115.91,7.71 ; K2.3 117.12,6.5 ; K6.3 136.32,13.93 ; K6.3 136.32,11.5 ; K6.3 137.54,12.71 ; K6.3 135.11,12.71 ; K2.4 123.47,8.93 ; K2.4 124.69,7.71 ; K2.4 123.47,6.5 ; K2.4 122.26,7.71 ; USBH2.4 168.26,50.48 ; USBH2.4 167.12,51.63 ; USBH2.4 165.98,50.48 ; USBH2.4 167.12,49.34 ; 140.08,98.55 139.03,97.5 CON11.2 ; K7.4 161.67,8.93 ; K7.4 161.67,6.5 ; K7.4 160.46,7.71 ; K7.4 162.89,7.71 ; CON5.B 130.1,121.92 ; CON5.B 130.1,116.28 ; CON5.B 127.28,119.1 ; CON5.B 132.92,119.1 ; CON5.A 132.92,127.1 ; CON5.A 127.28,127.1 ; CON5.A 130.1,124.28 ; CON8.2 14.33,21.02 ; CON8.2 13.25,19.94 ; CON8.2 14.33,18.86 ; CON8.2 15.41,19.94 ; 135.11,2.71 K5.3 ; K5.3 137.54,2.71 ; K5.3 136.32,1.5 ; K5.3 136.32,3.93 ; 174.75,77.85 175.62,76.98 LCD3.20 ; 42.87,119.01 COM1.5 ; COM1.5 44.01,117.86 ; COM1.5 44.01,120.15 ; 110.11,92.58 109.03,91.5 CON5.1 109,90.14 ; RST.4 37.21,40.32 ; RST.4 37.21,37.89 ; RST.4 38.43,39.1 ; RST.4 35.99,39.1 ; CN1.3 11.77,9.01 ; CN1.3 9.36,9.01 ; CN1.3 10.56,7.7 ; CN1.3 10.56,10.31 ; 141.46,12.71 K6.4 ; K6.4 142.67,11.5 ; K6.4 143.89,12.71 ; K6.4 142.67,13.93 ; USBH1.4 168.26,119.51 ; USBH1.4 167.12,118.36 ; USBH1.4 167.12,120.65 ; 127.95,91.5 CON5.19 127,90.55 ; CON7.3 9.34,113 ; CON7.3 7.5,114.84 ; CON7.3 5.66,113 ; CON7.3 7.5,111.16 ; 155.32,6.5 K7.3 ; K7.3 155.32,8.93 ; K7.3 156.54,7.71 ; K7.3 154.11,7.71 ; 113.87,6.5 K1.4 ; K1.4 115.09,7.71 ; K1.4 113.87,8.93 ; K1.4 112.66,7.71 ; 6,101.07 TINY6410.A2 5.07,102 ; 41.97,111 CON4.4 43.12,112.65
  vias: v1(0.89,122.56) v1(0.89,120.02) v1(0.89,117.47) v1(0.89,114.94) v1(0.89,112.39) v1(0.89,109.86) v1(0.89,107.31) v1(0.89,104.78) v1(0.89,102.23) v1(0.89,99.69) v1(0.89,97.16) v1(0.89,94.61) v1(0.89,92.08) v1(0.89,89.53) v1(0.89,87) v1(0.89,84.45) v1(0.89,81.92) v1(0.89,79.38) v1(0.89,76.83) v1(0.89,74.3) v1(0.89,71.75) v1(0.89,69.22) v1(0.89,66.67) v1(0.89,64.14) v1(0.89,61.59) v1(0.89,59.05) v1(0.89,56.52) v1(0.89,53.98) v1(0.89,51.44) v1(0.89,48.9) v1(0.89,46.35) v1(0.89,43.81) v1(0.89,41.27) v1(0.89,38.73) v1(0.89,36.2) v1(0.89,33.66) v1(0.89,31.11) v1(0.89,28.57) v1(0.89,26.04) v1(0.89,23.5) v1(0.89,20.95) v1(0.89,18.41) v1(0.89,15.88) v1(1.02,8.89) v1(3.43,120.02) v1(3.43,117.47) v1(3.43,114.94) v1(3.43,112.39) v1(3.43,107.31) v1(3.43,104.78) v1(3.43,46.35) v1(3.43,43.81) v1(3.43,41.27) v1(3.43,38.73) v1(3.43,36.2) v1(3.43,33.66) v1(3.43,31.11) v1(3.94,101.22) v1(3.94,99.44) v1(3.94,97.16) v1(3.94,94.61) v1(3.94,92.08) v1(3.94,89.53) v1(3.94,87) v1(3.94,84.45) v1(3.94,81.92) v1(3.94,79.38) v1(3.94,76.83) v1(3.94,74.3) v1(3.94,71.75) v1(3.94,69.22) v1(3.94,66.67) v1(3.94,64.14) v1(5.68,12.48) v1(5.97,120.02) v1(5.97,46.35) v1(5.97,43.81) v1(5.97,41.27) v1(5.97,38.73) v1(5.97,36.2) v1(5.97,33.66) v1(5.97,31.11) v1(6.8,29.94) v1(7.62,8.38) v1(7.75,0.89) v1(7.87,120.65) v1(7.87,4.45) v1(8.13,61.72) v1(8.33,100.1) v1(8.26,28.07) v1(8.38,116.84) v1(8.36,98.58) v1(8.51,127.64) v1(8.51,125.09) v1(8.51,122.56) v1(8.51,92.08) v1(8.51,89.53) v1(8.51,87) v1(8.51,84.45) v1(8.51,81.92) v1(8.51,79.38) v1(8.51,76.83) v1(8.51,74.3) v1(8.51,71.75) v1(8.51,69.22) v1(8.51,46.35) v1(8.51,43.81) v1(8.51,41.27) v1(8.51,38.73) v1(8.51,36.2) v1(8.51,33.66) v1(8.51,31.11) v1(8.64,109.35) v1(8.64,107.19) v1(9.4,128.91) v1(9.91,64.14) v1(10.02,4.96) v1(10.1,6.44) v1(10.15,54.79) v1(10.15,53.39) v1(10.34,100.1) v1(10.34,98.27) v1(10.29,0.89) v1(10.41,123.57) v1(10.36,61.49) v1(10.79,28.07) v1(11.05,127.64) v1(11.05,125.09) v1(11.05,89.53) v1(11.05,87) v1(11.05,84.45) v1(11.05,81.92) v1(11.05,79.38) v1(11.05,76.83) v1(11.05,74.3) v1(11.05,71.75) v1(11.05,46.35) v1(11.05,43.81) v1(11.05,41.27) v1(11.05,38.73) v1(11.05,36.2) v1(11.05,33.66) v1(11.05,31.11) v1(11.15,56.87) v1(11.3,54.1) v1(11.43,65.53) v1(11.94,128.91) v1(12.32,114.94) v1(12.32,98.22) v1(12.37,99.95) v1(12.43,61.59) v1(13.08,67.18) v1(13.16,56.82) v1(13.34,28.07) v1(13.59,87) v1(13.59,84.45) v1(13.59,81.92) v1(13.59,79.38) v1(13.59,76.83) v1(13.59,74.3) v1(13.59,46.35) v1(13.59,43.81) v1(13.59,41.27) v1(13.59,38.73) v1(13.59,36.2) v1(13.59,33.66) v1(13.59,31.11) v1(13.72,4.7) v1(13.84,54.1) v1(13.97,0.89) v1(14.17,99.24) v1(14.22,97.84) v1(14.48,128.91) v1(14.61,68.83) v1(15.39,5.56) v1(15.37,0.89) v1(16.13,84.45) v1(16.13,81.92) v1(16.13,79.38) v1(16.13,76.83) v1(16.13,74.3) v1(16.38,54.1) v1(16.38,51.56) v1(16.51,61.34) v1(16.68,64.35) v1(17.12,99.09) v1(17.14,69.34) v1(17.22,97.26) v1(17.65,21.21) v1(17.91,0.89) v1(18.03,4.45) v1(18.41,28.07) v1(18.54,61.59) v1(18.67,48.9) v1(18.67,46.35) v1(18.67,43.81) v1(18.67,41.27) v1(18.67,38.73) v1(18.67,36.2) v1(18.67,33.66) v1(18.67,31.11) v1(18.92,54.1) v1(18.92,51.56) v1(20.32,8.38) v1(20.45,0.89) v1(20.57,120.78) v1(20.57,4.45) v1(20.83,69.24) v1(20.95,118.39) v1(20.95,79.63) v1(20.95,77.09) v1(20.95,74.55) v1(20.98,71.98) v1(20.95,61.85) v1(20.95,28.07) v1(21.21,48.9) v1(21.21,46.35) v1(21.21,43.81) v1(21.21,41.27) v1(21.21,38.73) v1(21.21,36.2) v1(21.21,33.66) v1(21.21,31.11) v1(21.36,92.23) v1(21.46,54.1) v1(21.46,51.56) v1(21.84,69.22) v1(22.61,91.01) v1(22.61,62.1) v1(22.73,17.53) v1(22.73,14.22) v1(22.96,99.21) v1(22.99,20.32) v1(22.99,0.89) v1(23.09,97.66) v1(23.11,4.45) v1(23.34,77.09) v1(23.34,74.55) v1(23.37,71.98) v1(24.26,45.84) v1(24.41,61.95) v1(25.4,122.94) v1(25.53,0.89) v1(25.65,73.91) v1(25.65,49.28) v1(25.65,4.45) v1(26.04,52.07) v1(26.29,17.4) v1(26.29,14.1) v1(26.92,92.84) v1(26.92,33.02) v1(27.56,85.85) v1(27.94,41.91) v1(28.07,0.89) v1(28.24,98.91) v1(28.19,4.45) v1(28.32,8.26) v1(29.08,54.36) v1(29.59,83.82) v1(29.84,55.75) v1(30.35,73.53) v1(30.61,62.61) v1(30.61,0.89) v1(30.73,96.27) v1(30.73,4.45) v1(30.86,8.26) v1(31.11,82.04) v1(32.13,95) v1(32.59,54.76) v1(32.89,98.17) v1(32.89,80.26) v1(33.15,0.89) v1(33.27,4.45) v1(33.66,93.47) v1(33.91,112.95) v1(34.42,85.47) v1(34.54,73.79) v1(34.57,100.1) v1(34.8,128.91) v1(35.31,91.69) v1(35.31,33.78) v1(35.69,0.89) v1(35.76,110.52) v1(35.81,56.26) v1(35.81,4.45) v1(36.6,83.08) v1(36.78,94.18) v1(37.21,89.79) v1(37.34,128.91) v1(37.34,73.79) v1(38.1,81.53) v1(38.23,0.89) v1(38.35,97.54) v1(38.35,4.45) v1(38.81,110.54) v1(38.99,107.19) v1(39.37,49.66) v1(39.5,45.85) v1(39.5,42.29) v1(39.75,90.93) v1(39.75,50.8) v1(39.88,128.91) v1(39.9,41.22) v1(40.01,73.79) v1(40.01,34.29) v1(40.13,87.25) v1(40.23,100.38) v1(40.28,125.76) v1(40.36,98.48) v1(40.77,0.89) v1(40.89,53.34) v1(40.89,4.45) v1(41.02,56.03) v1(41.45,110.39) v1(42.06,107.19) v1(42.16,88.52) v1(42.29,73.79) v1(42.42,128.91) v1(42.55,84.71) v1(42.57,117.65) v1(42.67,51.69) v1(42.93,49.66) v1(43.1,125.5) v1(43.05,42.29) v1(43.31,87.38) v1(43.31,0.89) v1(43.43,4.45) v1(43.56,116.54) v1(43.56,53.21) v1(43.69,73.79) v1(44.07,100.33) v1(44.2,45.47) v1(44.27,112.65) v1(44.7,39.32) v1(44.96,128.91) v1(45.34,51.69) v1(45.59,89.92) v1(45.77,100.58) v1(45.85,73.79) v1(45.85,0.89) v1(46,56.29) v1(45.97,4.45) v1(46.35,86.87) v1(46.46,97.92) v1(46.48,49.66) v1(46.61,53.21) v1(46.61,45.85) v1(46.61,42.29) v1(46.61,38.73) v1(47.17,117.2) v1(47.5,128.91) v1(47.5,126.36) v1(47.78,87.68) v1(48.23,100.71) v1(48.51,86.36) v1(49.05,17.75) v1(49.43,117.5) v1(49.53,74.04) v1(49.66,41.91) v1(49.91,45.59) v1(49.91,13.08) v1(50.04,128.91) v1(50.04,126.36) v1(50.24,100.63) v1(50.16,38.1) v1(50.16,15.11) v1(50.83,50.04) v1(51.69,36.83) v1(52.06,94.07) v1(52.25,100.53) v1(52.37,117.27) v1(52.58,128.91) v1(52.58,126.36) v1(53.34,50.09) v1(53.47,84.71) v1(54.31,100.53) v1(55.12,128.91) v1(55.12,126.36) v1(55.45,112.9) v1(55.63,96.27) v1(55.63,84.84) v1(55.63,74.04) v1(55.88,93.6) v1(57.66,128.91) v1(57.66,126.36) v1(58.27,99.92) v1(58.32,96.24) v1(58.29,93.6) v1(58.42,86.11) v1(58.57,30.78) v1(59.36,49.45) v1(59.77,51.69) v1(59.89,53.16) v1(60.2,128.91) v1(60.2,126.36) v1(60.25,100.13) v1(60.25,96.19) v1(60.2,86.11) v1(60.3,93.98) v1(61.09,33.38) v1(61.34,73.94) v1(62.23,100.18) v1(62.18,96.04) v1(62.48,93.98) v1(62.48,85.85) v1(62.74,128.91) v1(62.74,126.36) v1(63.25,56.41) v1(63.75,71.5) v1(64.64,96.39) v1(64.64,93.73) v1(65.28,128.91) v1(65.28,126.36) v1(65.74,55.5) v1(67.06,34.54) v1(67.31,96.65) v1(67.31,93.73) v1(67.31,92.08) v1(67.56,103.25) v1(67.82,128.91) v1(67.82,126.36) v1(68.2,14.48) v1(68.71,72.26) v1(69.52,103.45) v1(70.03,20.24) v1(70.03,17.6) v1(70.36,128.91) v1(70.36,126.36) v1(70.64,112.7) v1(71.25,51.82) v1(71.25,49.02) v1(71.75,69.22) v1(72.01,91.31) v1(72.75,55.98) v1(72.9,128.91) v1(72.9,126.36) v1(73.03,46.99) v1(74.3,48.9) v1(74.32,17.27) v1(75.44,128.91) v1(75.44,126.36) v1(75.44,31.62) v1(76.07,52.58) v1(76.71,55.12) v1(76.83,93.22) v1(77.85,87) v1(77.98,128.91) v1(77.98,126.36) v1(77.98,61.11) v1(78.36,29.21) v1(78.61,56.77) v1(80.01,68.2) v1(80.52,128.91) v1(80.52,126.36) v1(81.04,88.23) v1(81.1,94.89) v1(82.45,68.2) v1(83.06,128.91) v1(83.06,126.36) v1(83.19,37.59) v1(84.45,54.1) v1(85.6,128.91) v1(85.6,126.36) v1(86.49,53.21) v1(86.72,107.16) v1(86.89,101.22) v1(88.14,128.91) v1(88.14,126.36) v1(88.59,65.12) v1(90.04,49.4) v1(90.17,47.12) v1(90.68,128.91) v1(90.68,126.36) v1(90.7,96.32) v1(90.81,109.6) v1(91.19,52.7) v1(93.22,128.91) v1(93.22,126.36) v1(93.22,63.5) v1(93.47,65.15) v1(94.64,96.44) v1(95.76,128.91) v1(95.76,126.36) v1(96.39,12.57) v1(96.52,11.18) v1(96.65,64.39) v1(98.3,128.91) v1(98.3,126.36) v1(99.26,3) v1(99.69,95.38) v1(99.78,100.5) v1(99.95,64.39) v1(100.84,128.91) v1(100.84,126.36) v1(101.22,22.1) v1(101.96,3) v1(102.23,35.31) v1(102.36,37.47) v1(102.49,17.91) v1(103.38,128.91) v1(103.63,16.76) v1(104.01,88.77) v1(104.65,64.39) v1(104.67,79.5) v1(104.9,56.64) v1(104.9,37.59) v1(104.9,33.78) v1(105.16,35.43) v1(106.55,89.79) v1(108.46,128.91) v1(108.48,9.6) v1(108.81,3.17) v1(109.09,89.53) v1(109.22,79.76) v1(110.11,53.34) v1(110.49,64.39) v1(110.62,32.38) v1(110.74,56.64) v1(111,128.91) v1(111,126.36) v1(111.12,94.87) v1(111.63,97.66) v1(112.14,32) v1(113.03,30.86) v1(113.28,19.43) v1(113.41,20.45) v1(113.54,128.91) v1(113.54,126.36) v1(114.68,10.29) v1(114.68,5.21) v1(115.7,96.65) v1(116.08,128.91) v1(116.08,126.36) v1(117.09,38.86) v1(117.09,5.21) v1(117.2,88.47) v1(117.73,34.8) v1(118.36,66.93) v1(118.62,128.91) v1(118.62,126.36) v1(119.25,96.65) v1(119.63,10.29) v1(119.63,7.75) v1(119.63,5.21) v1(119.76,36.2) v1(120.02,89.97) v1(120.27,116.97) v1(120.52,20.57) v1(121.16,128.91) v1(121.16,126.36) v1(121.41,32.13) v1(121.79,5.46) v1(121.92,7.75) v1(122.43,22.61) v1(123.7,128.91) v1(123.7,126.36) v1(124.36,29.44) v1(124.71,10.29) v1(124.71,5.21) v1(125.02,110.01) v1(124.99,82.37) v1(125.22,22.48) v1(125.35,25.4) v1(125.98,71.37) v1(126.24,128.91) v1(126.24,126.36) v1(126.42,89.97) v1(126.61,41.19) v1(127.25,5.21) v1(127.38,13.97) v1(128.52,24.38) v1(128.52,22.35) v1(128.63,93.93) v1(128.91,60.07) v1(129.16,13.84) v1(129.41,41.66) v1(129.46,91.72) v1(129.54,37.59) v1(129.79,10.29) v1(129.79,7.75) v1(129.79,5.21) v1(130.15,78.66) v1(130.45,93.85) v1(130.91,72.09) v1(131.06,21.59) v1(131.57,7.75) v1(131.95,5.21) v1(132.53,92.71) v1(132.46,70.74) v1(132.46,32.13) v1(132.59,63.12) v1(132.72,60.07) v1(132.72,56.26) v1(133.86,128.91) v1(133.86,126.36) v1(134.24,94.87) v1(134.22,80.54) v1(134.87,10.29) v1(134.87,5.21) v1(136.02,98.04) v1(136.27,32.13) v1(136.27,28.32) v1(136.4,128.91) v1(136.4,126.36) v1(136.4,63.12) v1(136.53,60.07) v1(136.53,56.26) v1(136.53,44.83) v1(136.78,77.98) v1(137.41,5.21) v1(137.54,79.38) v1(138.94,128.91) v1(138.94,126.36) v1(138.94,112.75) v1(139.81,72.74) v1(139.95,10.29) v1(139.95,5.21) v1(140.08,32.13) v1(140.08,28.32) v1(140.08,24.51) v1(140.34,60.07) v1(140.34,56.26) v1(140.34,44.83) v1(141.22,120.32) v1(141.48,128.91) v1(141.48,126.36) v1(143.89,32.13) v1(143.89,28.32) v1(143.89,24.51) v1(144.02,128.91) v1(144.02,126.36) v1(144.02,91.06) v1(144.02,63.12) v1(144.15,60.07) v1(144.15,56.26) v1(144.15,44.83) v1(145.03,10.16) v1(145.16,76.76) v1(145.41,16.89) v1(145.67,20.07) v1(145.8,78.61) v1(146.56,128.91) v1(146.56,126.36) v1(147.7,32.13) v1(147.7,28.32) v1(147.83,63.12) v1(147.96,60.07) v1(147.96,56.26) v1(147.96,48.64) v1(147.96,44.83) v1(148.46,83.31) v1(148.46,78.49) v1(148.62,76.71) v1(148.97,10.16) v1(149.1,128.91) v1(149.1,126.36) v1(149.35,100.43) v1(150.11,10.16) v1(150.11,7.62) v1(150.11,5.08) v1(150.98,111.63) v1(151,20.83) v1(151,17.14) v1(151.26,84.96) v1(151.26,78.49) v1(151.38,86.36) v1(151.38,76.96) v1(151.64,128.91) v1(151.64,126.36) v1(151.64,32.38) v1(151.64,28.57) v1(151.64,24.77) v1(151.76,60.07) v1(151.89,56.39) v1(151.89,52.58) v1(151.89,48.77) v1(151.89,44.96) v1(153.29,100.05) v1(154.18,128.91) v1(154.26,87.94) v1(154.56,81.92) v1(154.56,77.22) v1(154.69,80.01) v1(155.19,10.16) v1(155.19,5.08) v1(155.3,99.85) v1(155.57,61.21) v1(155.7,56.39) v1(155.7,52.58) v1(155.7,48.77) v1(155.7,44.96) v1(157.35,100.63) v1(157.73,58.67) v1(157.73,7.62) v1(158.12,5.21) v1(158.88,81.28) v1(159.64,55.37) v1(159.77,128.93) v1(160.15,70.1) v1(160.27,10.16) v1(160.27,5.08) v1(161.8,128.91) v1(161.8,126.36) v1(162.56,22.35) v1(162.81,27.18) v1(163.7,73.53) v1(165.35,26.8) v1(165.35,5.08) v1(167,102.62) v1(167,69.47) v1(167.03,24.36) v1(167.89,7.62) v1(168.07,62.38) v1(168.94,47.6) v1(169.16,101.09) v1(169.42,128.91) v1(169.42,126.36) v1(169.42,103.5) v1(169.54,106.05) v1(169.93,66.67) v1(170.56,16.64) v1(171.32,65.15) v1(171.7,101.09) v1(171.88,61.06) v1(171.96,128.91) v1(171.96,114.43) v1(171.96,103.5) v1(172.09,111.12) v1(172.09,70.74) v1(172.97,63.63) v1(173.38,56.26) v1(173.38,52.7) v1(173.35,7.87) v1(173.61,80.26) v1(174.5,121.28) v1(174.5,118.75) v1(174.5,116.2) v1(174.5,113.67) v1(174.62,111.12) v1(174.73,67.23) v1(174.75,92.71) v1(176.15,40.64) v1(177.04,121.28) v1(177.04,118.75) v1(177.04,113.67) v1(177.16,111.12) v1(178.94,94.23) v1(178.94,50.8) v1(178.94,48.26) v1(178.94,45.72) v1(178.94,43.18) v1(178.94,40.64) v1(178.94,33.02) v1(178.94,30.48) v1(178.94,22.86) v1(178.94,20.32) v1(178.94,17.78) v1(178.94,15.24) v1(178.94,12.7) v1(178.94,10.16) v1(178.94,7.62) v1(179.07,123.83) v1(179.07,121.28) v1(179.07,118.75) v1(179.07,116.2) v1(179.07,113.67) v1(179.07,111.12) v1(179.07,108.58) v1(179.07,106.05) v1(179.07,103.5) v1(179.07,100.97) v1(179.07,98.42) v1(179.07,92.33) v1(179.07,90.3) v1(179.07,83.82) v1(179.07,82.17) v1(179.07,80.01) v1(179.07,76.33) v1(179.07,74.3) v1(179.07,72.26) v1(179.07,66.17) v1(179.07,64.01) v1(179.07,62.1)
